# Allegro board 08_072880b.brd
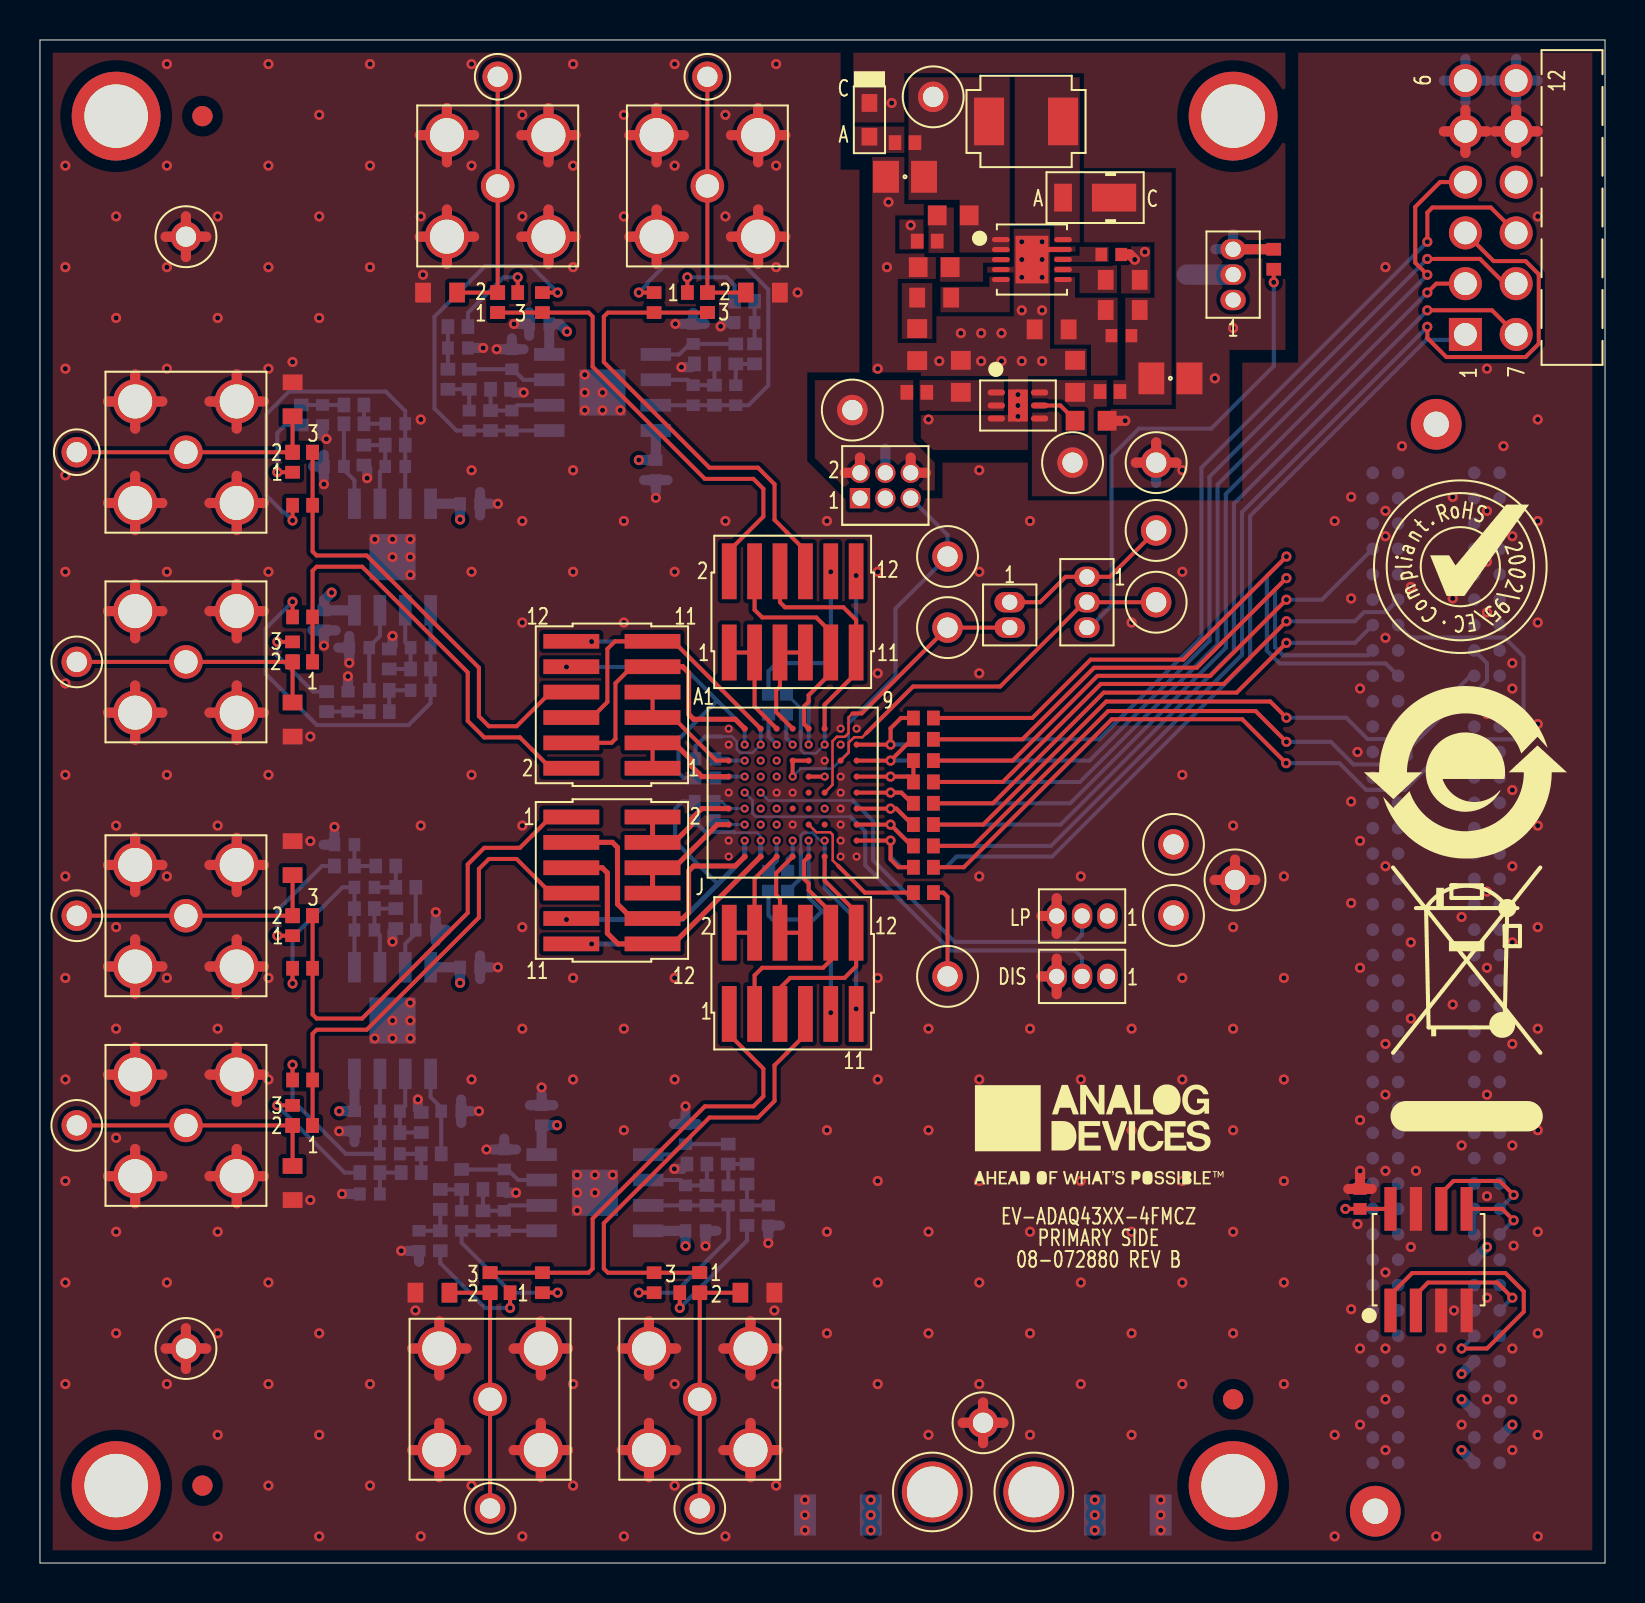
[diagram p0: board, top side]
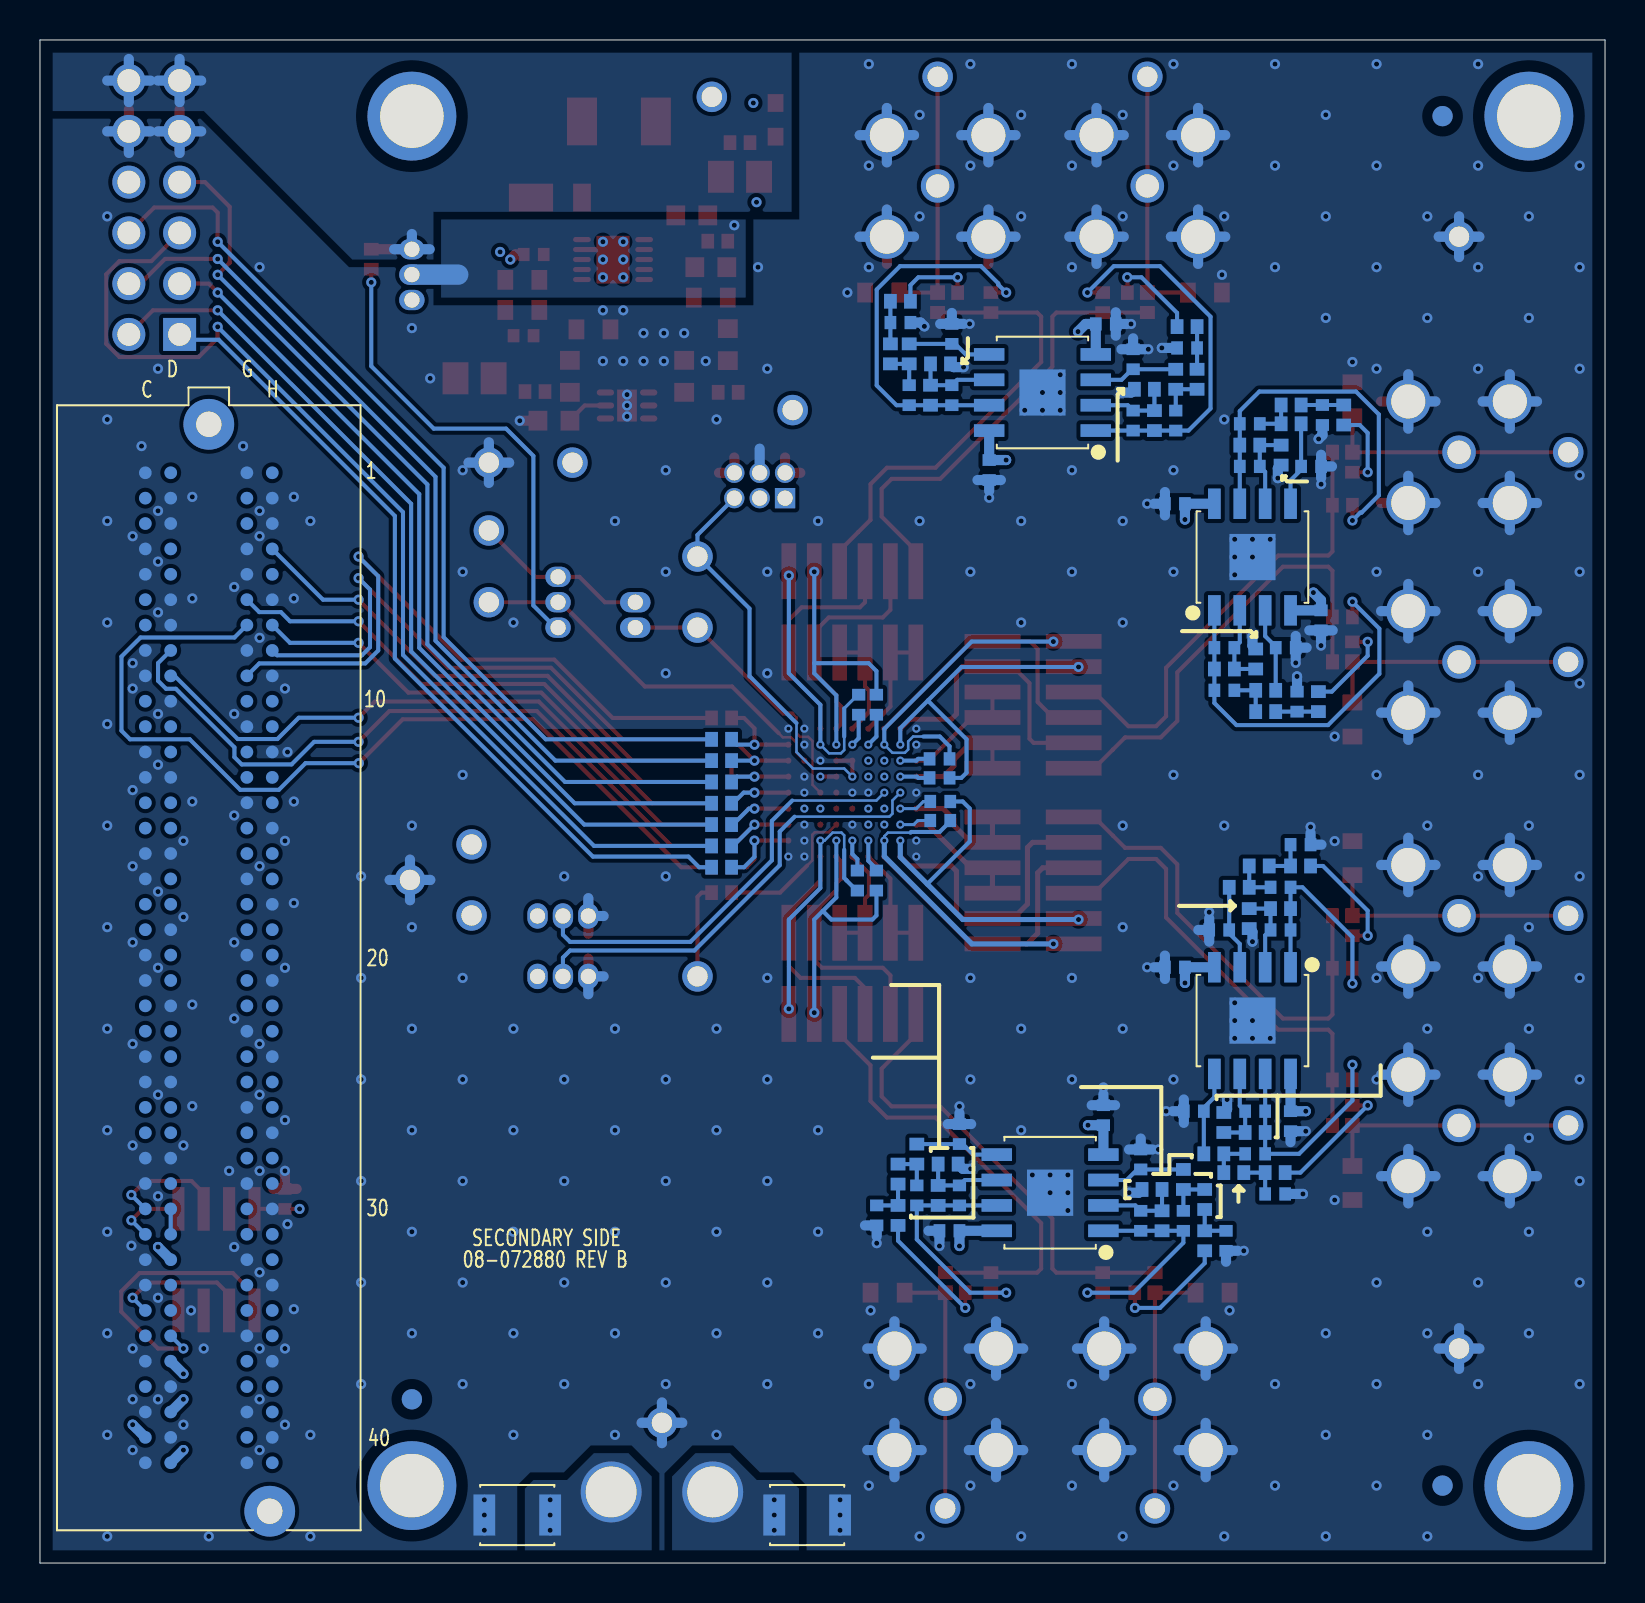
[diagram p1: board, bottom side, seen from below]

Outline 78.3 x 76.2 mm; copper layers: TOP, L2_GND, L3_PWR, BOTTOM. Coordinates in mm from the lower left corner of the outline.
Outline path: 0,76.2 0,0 78.3,0 78.3,76.2 0,76.2

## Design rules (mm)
constraint set DEFAULT: min track width 0.203
net group AINA: nets AINA+ AINA-
net group AINB: nets AINB+ AINB-
net group AINC: nets AINC+ AINC-
net group AIND: nets AIND+ AIND-

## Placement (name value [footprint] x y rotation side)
A1  ADA4625-2ARDZ  [SO8NB-PAD2_3X2_3]  27.76 18.53 90 bottom
A2  ADA4625-2ARDZ  [SO8NB-PAD2_3X2_3]  17.64 27.14 0 bottom
A3  ADA4625-2ARDZ  [SO8NB-PAD2_3X2_3]  17.64 50.33 180 bottom
A4  ADA4625-2ARDZ  [SO8NB-PAD2_3X2_3]  28.14 58.56 90 bottom
A+  RED  [CNKEY5001TP]  22.52 2.73 0 top
A-  RED  [CNKEY5001TP]  33.01 2.73 0 top
B+  RED  [CNKEY5001TP]  1.84 32.39 0 top
B-  RED  [CNKEY5001TP]  1.84 21.89 0 top
C1  TBD0402  [C0402]  36.45 34.15 270 bottom
C2  TBD0402  [C0402]  37.4 34.15 270 bottom
C3  TBD0402  [C0402]  33.26 38.1 180 bottom
C4  TBD0402  [C0402]  33.26 37.15 180 bottom
C5  TBD0402  [C0402]  33.29 39.28 180 bottom
C6  TBD0402  [C0402]  33.29 40.23 180 bottom
C7  TBD0402  [C0402]  36.45 42.94 90 bottom
C8  TBD0402  [C0402]  37.34 42.94 90 bottom
C9  0.1uF  [C0402]  66.04 18.22 90 top
C10  4.7UF  [C0805H60]  43.28 69.35 180 top
C11  2.2NF  [C0402]  53.59 65.47 180 top
C12  4.7UF  [C0805H60]  56.55 59.27 0 top
C13  2.2uF  [C0603]  51.78 59.37 90 top
C14  1NF  [C0603]  52.58 57.15 180 top
C15  2.2uF  [C0603]  46.07 59.37 90 top
C16  TBD0402  [C0402]  18.96 16.12 270 bottom
C17  TBD0402  [C0402]  36.44 17.39 270 bottom
C18  TBD0402  [C0402]  23.23 20.19 90 bottom
C19  TBD0402  [C0402]  32.3 21.46 90 bottom
C20  TBD0402  [C0402]  21.09 17.12 270 bottom
C21  TBD0402  [C0402]  34.43 18.39 270 bottom
C22  TBD0402  [C0402]  32.8 16.62 0 bottom
C23  TBD0402  [C0402]  25.1 22.41 90 bottom
C24  TBD0402  [C0402]  23.23 17.12 270 bottom
C25  TBD0402  [C0402]  32.3 18.39 270 bottom
C26  1uF  [C0603]  44.74 64.83 180 top
C27  150pF  [C0603]  43.88 60.96 90 top
C28  4.7pF  [C0402]  54.1 61.4 0 top
C29  TBD0402  [C0402]  15.23 35.94 180 bottom
C30  TBD0402  [C0402]  16.5 18.47 180 bottom
C31  TBD0402  [C0402]  19.3 31.67 0 bottom
C32  TBD0402  [C0402]  20.57 22.61 0 bottom
C33  TBD0402  [C0402]  16.23 33.81 180 bottom
C34  TBD0402  [C0402]  17.5 20.47 180 bottom
C35  TBD0402  [C0402]  15.73 22.11 270 bottom
C36  TBD0402  [C0402]  21.52 29.81 0 bottom
C37  TBD0402  [C0402]  16.23 31.67 180 bottom
C38  TBD0402  [C0402]  17.5 22.61 180 bottom
C39  TBD0402  [C0402]  15.41 43.1 90 bottom
C40  TBD0402  [C0402]  14.14 57.44 270 bottom
C41  TBD0402  [C0402]  15.97 45.8 180 bottom
C42  TBD0402  [C0402]  14.7 54.86 180 bottom
C43  TBD0402  [C0402]  19.04 43.66 0 bottom
C44  TBD0402  [C0402]  17.77 57 0 bottom
C45  TBD0402  [C0402]  21.52 53 0 bottom
C46  TBD0402  [C0402]  14.21 47.16 270 bottom
C47  TBD0402  [C0402]  19.04 45.8 0 bottom
C48  TBD0402  [C0402]  17.77 54.86 0 bottom
C49  TBD0402  [C0402]  20.91 60.79 0 bottom
C50  TBD0402  [C0402]  35.25 62.06 180 bottom
C51  TBD0402  [C0402]  23.61 60.23 90 bottom
C52  TBD0402  [C0402]  32.68 61.5 90 bottom
C53  TBD0402  [C0402]  21.48 57.16 270 bottom
C54  TBD0402  [C0402]  34.81 58.43 270 bottom
C55  TBD0402  [C0402]  30.81 54.68 270 bottom
C56  TBD0402  [C0402]  24.98 61.99 180 bottom
C57  TBD0402  [C0402]  23.61 57.16 270 bottom
C58  TBD0402  [C0402]  32.68 58.43 270 bottom
C59  10uF  [C1210H106]  39.92 2.4 180 bottom
C60  10uF  [C1210H106]  54.42 2.4 0 bottom
C+  RED  [CNKEY5001TP]  1.84 45.09 0 top
C-  RED  [CNKEY5001TP]  1.84 55.58 0 top
D1  DFLS260-7  [POWERDI123]  52.79 68.31 180 top
D+  RED  [CNKEY5001TP]  22.9 74.36 0 top
D-  RED  [CNKEY5001TP]  33.39 74.36 0 top
DS1  SML-D12P8WT86  [LED0603_A]  41.5 72.2 270 top
E1  600OHMS  [L0603]  45.69 67.42 180 top
ENABLE  FTS-103-01-F-S  [CN1X3H159]  53.4 29.35 180 top
GND1  BLK  [CNKEY5001TP]  55.84 55.05 0 top
GND2  BLK  [CNKEY5001TP]  59.79 34.18 0 top
GND3  BLK  [CNKEY5001TP]  7.3 10.73 0 top
GND4  BLK  [CNKEY5001TP]  47.18 7.02 0 top
GND5  BLK  [CNKEY5001TP]  7.3 66.36 0 top
IN_LDO  WHT  [CNKEY5001TP]  45.4 50.36 0 top
INA+  131-3701-261  [CNJOHNSON131-3701-261]  22.52 8.19 0 top
INA-  131-3701-261  [CNJOHNSON131-3701-261]  33.01 8.19 0 top
INB+  131-3701-261  [CNJOHNSON131-3701-261]  7.3 32.39 0 top
INB-  131-3701-261  [CNJOHNSON131-3701-261]  7.3 21.89 0 top
INC+  131-3701-261  [CNJOHNSON131-3701-261]  7.3 45.09 0 top
INC-  131-3701-261  [CNJOHNSON131-3701-261]  7.3 55.58 0 top
IND+  131-3701-261  [CNJOHNSON131-3701-261]  22.9 68.9 0 top
IND-  131-3701-261  [CNJOHNSON131-3701-261]  33.39 68.9 0 top
J1  FTS-103-01-F-S  [CN1X3H159]  59.69 63.19 90 top
J2  FTS-103-01-F-S  [CN1X3H159]  52.38 49.34 270 top
J3  FTS-103-01-F-D  [CNTHMHDR2X3L150W135H164]  41.02 53.28 0 top
JP1  0  [3PINJUMPER_0402]  22.52 13.53 270 top
JP2  0  [3PINJUMPER_0402]  33.01 13.53 0 top
JP3  JMPR_0402  [R0402]  25.13 14.03 90 top
JP4  JMPR_0402  [R0402]  30.72 14.03 90 top
JP5  0  [3PINJUMPER_0402]  12.64 32.39 180 top
JP6  0  [3PINJUMPER_0402]  12.64 21.89 270 top
JP7  JMPR_0402  [R0402]  13.14 29.76 0 top
JP8  JMPR_0402  [R0402]  13.14 24.17 0 top
JP9  0  [3PINJUMPER_0402]  12.64 45.09 270 top
JP10  0  [3PINJUMPER_0402]  12.64 55.58 180 top
JP11  JMPR_0402  [R0402]  13.14 47.33 0 top
JP12  JMPR_0402  [R0402]  13.14 52.92 0 top
JP13  0  [3PINJUMPER_0402]  22.9 63.56 180 top
JP14  0  [3PINJUMPER_0402]  33.39 63.56 90 top
JP15  JMPR_0402  [R0402]  25.13 63.06 270 top
JP16  JMPR_0402  [R0402]  30.72 63.06 270 top
L1  6.8UH  [LSMSQ160H79]  49.33 72.12 0 top
LKA  FTS-106-01-L-DV  [CNSMMHDR2X6L300W135H180]  37.66 29.5 0 top
LKB  FTS-106-01-L-DV  [CNSMMHDR2X6L300W135H180]  28.61 34.15 270 top
LKC  FTS-106-01-L-DV  [CNSMMHDR2X6L300W135H180]  28.61 42.94 90 top
LKD  FTS-106-01-L-DV  [CNSMMHDR2X6L300W135H180]  37.66 47.59 0 top
MODE  FTS-103-01-F-S  [CN1X3H159]  53.4 32.37 180 top
NOREF  -  []  2.1 0 0 top
NOREF#2  -  []  0 76.2 0 top
NOREF#3  -  [unnamed#2]  59.69 72.39 0 top
NOREF#4  -  []  0 76.2 0 top
NOREF#5  -  [unnamed#2]  8.13 3.87 0 top
NOREF#6  -  []  -107.38 -168.53 0 top
NOREF#7  -  []  94.21 -80.45 0 top
NOREF#8  -  []  78.3 76.2 180 top
NOREF#9  -  []  80.64 38.48 0 top
NOREF#10  -  []  59.86 -66.1 180 top
NOREF#11  -  []  78.3 0 0 top
NOREF#12  -  []  253.56 264.16 270 top
NOREF#13  -  []  -107.38 -168.53 0 top
NOREF#14  -  [unnamed#2]  59.69 3.87 0 top
NOREF#15  -  []  78.3 0 90 top
NOREF#16  -  []  2.1 76.2 270 top
NOREF#17  -  []  94.24 -56.32 0 top
NOREF#18  -  []  3.81 3.87 0 top
NOREF#19  -  []  71.06 49.85 0 top
NOREF#20  -  []  -107.38 -168.53 0 top
NOREF#21  -  []  502.48 43.18 0 top
NOREF#22  -  []  52.68 21.4 0 top
NOREF#23  -  [unnamed#2]  59.69 8.19 0 top
NOREF#24  -  [unnamed#2]  3.81 3.87 0 top
NOREF#25  -  [unnamed#2]  8.13 72.39 0 top
NOREF#26  -  []  94.24 -56.32 0 top
NOREF#27  -  []  -37.15 209.23 0 top
NOREF#28  -  []  0 0 0 top
NOREF#29  -  []  93.96 -18.22 0 top
NOREF#30  -  []  78.3 0 90 top
NOREF#31  -  [unnamed#2]  3.81 72.39 0 top
NOREF#32  -  []  5.38 74.74 0 top
NOREF#33  -  []  105.98 106.68 0 top
NOREF#34  -  []  45.49 1.39 0 top
NOREF#35  -  []  71.31 39.56 0 top
NOREF#36  -  []  253.56 303.53 0 top
NOREF#37  -  []  3.81 3.87 0 top
NOREF#38  -  []  0 0 0 top
NOREF#39  -  [unnamed#2]  8.13 72.39 180 bottom
NOREF#40  -  [unnamed#2]  8.13 3.87 180 bottom
NOREF#41  -  [unnamed#2]  59.69 8.19 180 bottom
OUT_LDO  RED  [CNKEY5001TP]  55.84 51.66 0 top
P1  ASP-134604-01  [CNSAMTECASP-134604-01]  69.85 29.78 270 bottom
P2  TSW-106-25-F-D-RA  [CNHDRRA2X6H240]  71.31 61.47 90 top
P3  FTS-102-01-F-S  [CNSAMTECFTS-102-01-F-S]  48.51 48.07 270 top
R1  TBD0603  [R0603]  19.63 13.53 0 top
R2  TBD0603  [R0603]  35.89 13.53 180 top
R3  TBD0603  [R0603]  12.64 35.27 270 top
R4  TBD0603  [R0603]  12.64 19.01 90 top
R5  TBD0603  [R0603]  12.64 42.2 90 top
R6  TBD0603  [R0603]  12.64 58.22 270 top
R7  TBD0603  [R0603]  20.02 63.56 0 top
R8  TBD0603  [R0603]  36.16 63.56 180 top
R9  TBD0402  [R0402]  20.03 16.12 90 bottom
R10  0  [R0402]  61.72 65.23 270 top
R11  TBD0402  [R0402]  35.37 17.39 90 bottom
R12  TBD0402  [R0402]  20.03 18.19 90 bottom
R13  0  [R0402]  44.2 35.88 0 top
R14  0  [R0402]  44.2 36.94 0 top
R15  0  [R0402]  44.2 39.08 0 top
R16  0  [R0402]  44.2 34.81 0 top
R17  0  [R0402]  44.2 42.28 0 top
R18  TBD0402  [R0402]  35.37 19.46 90 bottom
R19  0  [R0402]  44.2 38.01 0 top
R20  0  [R0402]  44.2 41.21 0 top
R21  TBD0402  [R0402]  21.09 19.19 90 bottom
R22  TBD0402  [R0402]  34.43 20.46 90 bottom
R23  0  [R0402]  44.2 40.14 0 top
R24  0  [R0402]  44.2 34.81 0 bottom
R25  0  [R0402]  44.2 38.01 0 bottom
R26  0  [R0402]  44.2 35.88 0 bottom
R27  0  [R0402]  44.2 39.08 0 bottom
R28  0  [R0402]  44.2 36.94 180 bottom
R29  0  [R0402]  44.2 40.14 180 bottom
R30  TBD0402  [R0402]  22.66 18.69 180 bottom
R31  97.6K  [R0603]  54.17 62.69 180 top
R32  34.8K  [R0603]  50.61 61.72 180 top
R33  0  [R0402]  53.53 58.61 180 top
R34  200  [R0402]  43.28 71.06 0 top
R35  TBD0402  [R0402]  32.86 19.96 0 bottom
R36  TBD0402  [R0402]  22.16 17.12 270 bottom
R37  TBD0402  [R0402]  33.36 18.39 270 bottom
R38  TBD0402  [R0402]  15.23 34.87 0 bottom
R39  TBD0402  [R0402]  16.5 19.53 0 bottom
R40  0  [R0402]  13.14 21.89 0 top
R41  TBD0402  [R0402]  17.3 34.87 0 bottom
R42  TBD0402  [R0402]  18.57 19.53 0 bottom
R43  0  [R0402]  13.14 32.39 0 top
R44  TBD0402  [R0402]  18.3 33.81 0 bottom
R45  TBD0402  [R0402]  19.57 20.47 0 bottom
R46  TBD0402  [R0402]  17.8 32.24 90 bottom
R47  TBD0402  [R0402]  19.07 22.04 270 bottom
R48  TBD0402  [R0402]  16.23 32.74 180 bottom
R49  TBD0402  [R0402]  17.5 21.54 180 bottom
R50  TBD0402  [R0402]  14.34 43.1 270 bottom
R51  20K  [R0603]  54.17 64.2 0 top
R52  56.2K  [R0603]  44.74 63.31 180 top
R53  0  [R0402]  44.39 66.14 0 top
R54  0  [R0402]  43.87 58.57 180 top
R55  TBD0402  [R0402]  13.07 57.44 90 bottom
R56  0  [R0402]  13.14 55.58 0 top
R57  TBD0402  [R0402]  16.97 42.6 0 bottom
R58  TBD0402  [R0402]  15.7 57.94 0 bottom
R59  0  [R0402]  13.14 45.09 0 top
R60  TBD0402  [R0402]  16.97 43.66 180 bottom
R61  TBD0402  [R0402]  15.7 57 180 bottom
R62  TBD0402  [R0402]  17.48 45.23 270 bottom
R63  TBD0402  [R0402]  16.21 55.43 90 bottom
R64  TBD0402  [R0402]  19.04 44.73 0 bottom
R65  TBD0402  [R0402]  17.77 55.93 0 bottom
R66  TBD0402  [R0402]  20.91 61.86 180 bottom
R67  TBD0402  [R0402]  35.25 63.13 0 bottom
R68  0  [R0402]  44.2 41.21 180 bottom
R69  0  [R0402]  33.39 63.06 270 top
R70  0  [R0402]  22.52 14.03 90 top
R71  0  [R0402]  33.01 14.03 90 top
R72  TBD0402  [R0402]  20.41 59.23 270 bottom
R73  TBD0402  [R0402]  35.75 60.5 270 bottom
R74  0  [R0402]  22.9 63.06 270 top
R75  TBD0402  [R0402]  21.48 59.23 90 bottom
R76  TBD0402  [R0402]  34.81 60.5 90 bottom
R77  TBD0402  [R0402]  23.04 58.72 180 bottom
R78  TBD0402  [R0402]  33.24 59.99 0 bottom
R79  TBD0402  [R0402]  22.54 57.16 270 bottom
R80  TBD0402  [R0402]  33.74 58.43 270 bottom
R81  TBD0402  [R0402]  44.2 33.54 0 top
REFS  WHT  [CNKEY5001TP]  45.4 29.35 0 top
U1  ADAQ4380-4  [BGA81H91]  37.66 38.54 270 top
U2  LT8362EDD#PBF  [DFN10_3X3_PAD2_38X1_64]  49.63 65.21 270 top
U3  ADP7142ACPZN5.0  [DFN6_2X2_PAD1_6X1]  48.93 57.91 270 top
U4  M24C02-RMN6TP  [SO8]  69.47 15.18 0 top
UNK3V3  RED  [CNKEY5001TP]  44.68 73.36 0 top
UNK+5V  RED  [CNKEY5001TP]  40.64 57.68 0 top
UNK+6V  RED  [CNKEY5001TP]  51.66 55.05 0 top
VCC  RED  [CNKEY5001TP]  45.4 46.8 0 top
VLOGIC  WHT  [CNKEY5001TP]  55.84 48.07 0 top
VNEG  2501-2-00-80-00-00-07-0  [CNMILLMAX2501]  49.72 3.56 0 top
VPOS  2501-2-00-80-00-00-07-0  [CNMILLMAX2501]  44.64 3.56 0 top
VS+  RED  [CNKEY5001TP]  56.71 32.4 0 top
VS-  ORG  [CNKEY5001TP]  56.71 35.95 0 top

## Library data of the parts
A1-A4 = ADA4625_2_V2: Tolerance: N/A; User Part Number: UPN; alternate symbols: (); part number: ADA4625_2_V2_SM-ADA4625-2ARDZ,E031176,SO8NB-PAD2_3X2_3; tolerance: N/A
A+ A- B+ B- C+ C- D+ D- OUT_LDO UNK3V3 UNK+5V UNK+6V VCC VS+ = CNTP1P: Tolerance: N/A; User Part Number: UPN; alternate symbols: (); part number: CNTP1P_TH-RED,E016323,CNKEY5001TP; tolerance: N/A
C1-C8 C16-C25 C29-C58 = CAP: User Part Number: UPN; alternate symbols: (C0402L_ALT,C0402L); part number: CAP_SM-TBD0402,TBD0402,TBD0402,E000381,C0402
C9 = CAP: User Part Number: UPN; Tolerance: 10; alternate symbols: (C0402L); part number: CAP_SM-0.1UF,16V,10,E028141,C0402; tolerance: 10
C10 C12 = CAP: Tolerance: 10; User Part Number: UPN; alternate symbols: (); part number: CAP_SM-4.7UF,16V,10,E058535,C0805H60; tolerance: 10
C11 = CAP: User Part Number: UPN; Tolerance: 20; alternate symbols: (C0402L); part number: CAP_SM-2.2NF,25V,20,E042791,C0402; tolerance: 20
C13 C15 = CAP: User Part Number: UPN; Tolerance: 10; alternate symbols: (C0603L); part number: CAP_SM-2.2UF,25V,10,E039850,C0603; tolerance: 10
C14 = CAP: User Part Number: UPN; Tolerance: 10; alternate symbols: (C0603L); part number: CAP_SM-1NF,100V,10,E042847,C0603; tolerance: 10
C26 = CAP: User Part Number: UPN; Tolerance: 10; alternate symbols: (C0603L); part number: CAP_SM-1UF,25V,10,E033832,C0603; tolerance: 10
C27 = CAP: User Part Number: UPN; Tolerance: 5; alternate symbols: (C0603L); part number: CAP_SM-150PF,50V,5,E030220,C0603; tolerance: 5
C28 = CAP: User Part Number: UPN; Tolerance: 0.05pF; alternate symbols: (C0402L); part number: CAP_SM-4.7PF,50V,0.05PF,E021938,C0402; tolerance: 0.05pF
C59 C60 = CAP: Tolerance: 10; User Part Number: UPN; alternate symbols: (); part number: CAP_SM-10UF,25V,10,E013830,C1210H106; tolerance: 10
D1 = DIOSCHOTTKY: User Part Number: UPN; Tolerance: N/A; alternate symbols: (); part number: DIOSCHOTTKY_SM-DFLS260-7,60V,N/A,E032987,POWERDI123; tolerance: N/A
DS1 = DIOLED: User Part Number: UPN; Tolerance: N/A; alternate symbols: (); part number: DIOLED_SM-SML-D12P8WT86,2.2V,N/A,E027457,LED0603_A; tolerance: N/A
E1 = FERRITE: User Part Number: UPN; Tolerance: 25; alternate symbols: (L0603L); part number: FERRITE_SM-600OHMS,25,E007179,L0603; tolerance: 25
ENABLE J1 J2 MODE = CN3P: Tolerance: N/A; User Part Number: UPN; alternate symbols: (); part number: CN3P_TH-FTS-103-01-F-S,E021702,CN1X3H159; tolerance: N/A
GND1-GND5 = CNTP1P: Tolerance: N/A; User Part Number: UPN; alternate symbols: (); part number: CNTP1P_TH-BLK,E005347,CNKEY5001TP; tolerance: N/A
IN_LDO REFS VLOGIC = CNTP1P: Tolerance: N/A; User Part Number: UPN; alternate symbols: (); part number: CNTP1P_TH-WHT,E006153,CNKEY5001TP; tolerance: N/A
INA+ INA- INB+ INB- INC+ INC- IND+ IND- = CNBNC5P: Tolerance: N/A; User Part Number: UPN; alternate symbols: (); part number: CNBNC5P_TH-131-3701-261,E012123,CNJOHNSON131-3701-261; tolerance: N/A
J3 = CN6P_ODD_EVEN: User Part Number: UPN; Tolerance: N/A; alternate symbols: (); part number: CN6P_ODD_EVEN_TH-FTS-103-01-F-D,E047281,CNTHMHDR2X3L150W135H164; tolerance: N/A
JP1 JP2 JP5 JP6 JP9 JP10 JP13 JP14 = RESJMPR_3P: User Part Number: UPN; Tolerance: JUMPER; alternate symbols: (3PINJUMPER_0402_AB, 3PINJUMPER_0402_BA); part number: RESJMPR_3P_SM-0,E003438,1/10W,JUMPER,3PINJUMPER_0402; tolerance: JUMPER
JP3 JP4 JP7 JP8 JP11 JP12 JP15 JP16 = RESJMPRSHRT: User Part Number: UPN; Tolerance: N/A; alternate symbols: (R0402L); part number: RESJMPRSHRT_SM-JMPR_0402,E039547,N/A,N/A,R0402; tolerance: N/A
L1 = IND: User Part Number: UPN; Tolerance: 20; alternate symbols: (); part number: IND_SM-6.8UH,20,E035159,LSMSQ160H79; tolerance: 20
LKA LKB LKC LKD = CN12P_ODD_EVEN: User Part Number: UPN; Tolerance: N/A; alternate symbols: (); part number: CN12P_ODD_EVEN_SM-FTS-106-01-L-DV,E049458,CNSMMHDR2X6L300W135H180; tolerance: N/A
P1 = CN160P_CDGH: User Part Number: UPN; Tolerance: N/A; alternate symbols: (CNSAMTECASP-134604-01_KITTRF); part number: CN160P_CDGH_SM-ASP-134604-01,E011383,CNSAMTECASP-134604-01; tolerance: N/A
P2 = CN12P_V3: User Part Number: UPN; Tolerance: N/A; alternate symbols: (); part number: CN12P_V3_TH-TSW-106-25-F-D-RA,E018495,CNHDRRA2X6H240; tolerance: N/A
P3 = CN2P: Tolerance: N/A; User Part Number: UPN; alternate symbols: (); part number: CN2P_TH-FTS-102-01-F-S,E021754,CNSAMTECFTS-102-01-F-S; tolerance: N/A
R1-R8 = RES: User Part Number: UPN; alternate symbols: (R0603L); part number: RES_SM-TBD0603,E004050,TBD0603,TBD0603,R0603
R9 R11 R12 R18 R21 R22 R30 R35-R39 R41 R42 R44-R50 R55 R57 R58 R60-R67 R72 R73 R75-R81 = RES: User Part Number: UPN; alternate symbols: (R0402L,R0402L_ALT); part number: RES_SM-TBD0402,E004049,TBD0402,TBD0402,R0402
R10 R33 R53 R54 = RES: User Part Number: UPN; Tolerance: JUMPER; alternate symbols: (R0402L); part number: RES_SM-0,E025232,1/16W,JUMPER,R0402; tolerance: JUMPER
R13-R17 R19 R20 R23-R29 R40 R43 R56 R59 R68-R71 R74 = RES: User Part Number: UPN; Tolerance: JUMPER; alternate symbols: (R0402L,R0402L_ALT); part number: RES_SM-0,E003438,1/10W,JUMPER,R0402; tolerance: JUMPER
R31 = RES: User Part Number: UPN; Tolerance: 1; alternate symbols: (R0603L); part number: RES_SM-97.6K,E031992,1/10W,1,R0603; tolerance: 1
R32 = RES: User Part Number: UPN; Tolerance: 1; alternate symbols: (R0603L); part number: RES_SM-34.8K,E036013,1/10W,1,R0603; tolerance: 1
R34 = RES: User Part Number: UPN; Tolerance: 1; alternate symbols: (R0402L); part number: RES_SM-200,E003753,1/10W,1,R0402; tolerance: 1
R51 = RES: User Part Number: UPN; Tolerance: 1; alternate symbols: (R0603L); part number: RES_SM-20K,E017927,1/10W,1,R0603; tolerance: 1
R52 = RES: User Part Number: UPN; Tolerance: 1; alternate symbols: (R0603L); part number: RES_SM-56.2K,E003709,1/10W,1,R0603; tolerance: 1
U1 = ADAQ4380_4: User Part Number: UPN; Tolerance: N/A; alternate symbols: (); part number: ADAQ4380_4_SM-ADAQ4380-4,E046961,BGA81H91; tolerance: N/A
U2 = ICLT8362: Tolerance: N/A; User Part Number: UPN; alternate symbols: (); part number: ICLT8362_SM-LT8362EDD#PBF,E033516,DFN10_3X3_PAD2_38X1_64; tolerance: N/A
U3 = ADP7142: User Part Number: UPN; Tolerance: N/A; alternate symbols: (); part number: ADP7142_SM-ADP7142ACPZN5.0,E023519,DFN6_2X2_PAD1_6X1; tolerance: N/A
U4 = ICM24CXX: Tolerance: N/A; User Part Number: UPN; alternate symbols: (); part number: ICM24CXX_SM-M24C02-RMN6TP,E018349,SO8; tolerance: N/A
VNEG VPOS = CNTP1P: User Part Number: UPN; Tolerance: N/A; alternate symbols: (); part number: CNTP1P_TH-2501-2-00-80-00-00-07-0,E031108,CNMILLMAX2501; tolerance: N/A
VS- = CNTP1P: Tolerance: N/A; User Part Number: UPN; alternate symbols: (); part number: CNTP1P_TH-ORG,E029026,CNKEY5001TP; tolerance: N/A

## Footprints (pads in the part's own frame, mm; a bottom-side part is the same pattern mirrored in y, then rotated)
3PINJUMPER_0402
  rect 0.737x0.635 smd: 1(0,1.001)
  rect 0.737x0.737 smd: 2(0,0)
  rect 0.635x0.737 smd: 3(-1.001,0)
BGA81H91
  round 0.305 smd: A1(-3.2,-3.2) A2(-3.2,-2.4) A3(-3.2,-1.6) A4(-3.2,-0.8) A5(-3.2,0) A6(-3.2,0.8) A7(-3.2,1.6) A8(-3.2,2.4) A9(-3.2,3.2) B1(-2.4,-3.2) B2(-2.4,-2.4) B3(-2.4,-1.6) B4(-2.4,-0.8) B5(-2.4,0) B6(-2.4,0.8) B7(-2.4,1.6) B8(-2.4,2.4) B9(-2.4,3.2) C1(-1.6,-3.2) C2(-1.6,-2.4) C3(-1.6,-1.6) C4(-1.6,-0.8) C5(-1.6,0) C6(-1.6,0.8) C7(-1.6,1.6) C8(-1.6,2.4) C9(-1.6,3.2) D1(-0.8,-3.2) D2(-0.8,-2.4) D3(-0.8,-1.6) D4(-0.8,-0.8) D5(-0.8,0) D6(-0.8,0.8) D7(-0.8,1.6) D8(-0.8,2.4) D9(-0.8,3.2) E1(0,-3.2) E2(0,-2.4) E3(0,-1.6) E4(0,-0.8) E5(0,0) E6(0,0.8) E7(0,1.6) E8(0,2.4) E9(0,3.2) F1(0.8,-3.2) F2(0.8,-2.4) F3(0.8,-1.6) F4(0.8,-0.8) F5(0.8,0) F6(0.8,0.8) F7(0.8,1.6) F8(0.8,2.4) F9(0.8,3.2) G1(1.6,-3.2) G2(1.6,-2.4) G3(1.6,-1.6) G4(1.6,-0.8) G5(1.6,0) G6(1.6,0.8) G7(1.6,1.6) G8(1.6,2.4) G9(1.6,3.2) H1(2.4,-3.2) H2(2.4,-2.4) H3(2.4,-1.6) H4(2.4,-0.8) H5(2.4,0) H6(2.4,0.8) H7(2.4,1.6) H8(2.4,2.4) H9(2.4,3.2) J1(3.2,-3.2) J2(3.2,-2.4) J3(3.2,-1.6) J4(3.2,-0.8) J5(3.2,0) J6(3.2,0.8) J7(3.2,1.6) J8(3.2,2.4) J9(3.2,3.2)
C0402
  rect 0.584x0.66 smd: 1(-0.5,0) 2(0.5,0)
C0603
  rect 0.94x0.991 smd: 1(-0.8,0) 2(0.8,0)
C0805H60
  rect 1.295x1.6 smd: 1(-0.953,0) 2(0.953,0)
C1210H106
  rect 1.092x2.057 smd: 1(-1.646,0) 2(1.646,0)
CN1X3H159
  oval 1.016x1.27 hole 0.762: 1(0,0) 2(1.27,0) 3(2.54,0)
CNHDRRA2X6H240
  rect 1.651x1.651 hole 1.143: 1(0,0)
  round 1.651 hole 1.143: 2(2.54,0) 3(5.08,0) 4(7.62,0) 5(10.16,0) 6(12.7,0) 7(0,-2.54) 8(2.54,-2.54) 9(5.08,-2.54) 10(7.62,-2.54) 11(10.16,-2.54) 12(12.7,-2.54)
CNJOHNSON131-3701-261
  round 1.676 hole 1.168: 1(0,0)
  round 2.21 hole 1.702: 2(-2.54,2.54) 3(2.54,2.54) 4(2.54,-2.54) 5(-2.54,-2.54)
CNKEY5001TP
  round 1.524 hole 1.016: 1(0,0)
CNMILLMAX2501
  round 3.048 hole 2.54: 1(0,0)
CNSAMTECASP-134604-01
  round 2.54 hole 1.27 unplated: (-27.191,0) (27.191,3.048)
  round 0.635 smd: C1(-24.765,-3.175) C2(-23.495,-3.175) C3(-22.225,-3.175) C4(-20.955,-3.175) C5(-19.685,-3.175) C6(-18.415,-3.175) C7(-17.145,-3.175) C8(-15.875,-3.175) C9(-14.605,-3.175) C10(-13.335,-3.175) C11(-12.065,-3.175) C12(-10.795,-3.175) C13(-9.525,-3.175) C14(-8.255,-3.175) C15(-6.985,-3.175) C16(-5.715,-3.175) C17(-4.445,-3.175) C18(-3.175,-3.175) C19(-1.905,-3.175) C20(-0.635,-3.175) C21(0.635,-3.175) C22(1.905,-3.175) C23(3.175,-3.175) C24(4.445,-3.175) C25(5.715,-3.175) C26(6.985,-3.175) C27(8.255,-3.175) C28(9.525,-3.175) C29(10.795,-3.175) C30(12.065,-3.175) C31(13.335,-3.175) C32(14.605,-3.175) C33(15.875,-3.175) C34(17.145,-3.175) C35(18.415,-3.175) C36(19.685,-3.175) C37(20.955,-3.175) C38(22.225,-3.175) C39(23.495,-3.175) C40(24.765,-3.175) D1(-24.765,-1.905) D2(-23.495,-1.905) D3(-22.225,-1.905) D4(-20.955,-1.905) D5(-19.685,-1.905) D6(-18.415,-1.905) D7(-17.145,-1.905) D8(-15.875,-1.905) D9(-14.605,-1.905) D10(-13.335,-1.905) D11(-12.065,-1.905) D12(-10.795,-1.905) D13(-9.525,-1.905) D14(-8.255,-1.905) D15(-6.985,-1.905) D16(-5.715,-1.905) D17(-4.445,-1.905) D18(-3.175,-1.905) D19(-1.905,-1.905) D20(-0.635,-1.905) D21(0.635,-1.905) D22(1.905,-1.905) D23(3.175,-1.905) D24(4.445,-1.905) D25(5.715,-1.905) D26(6.985,-1.905) D27(8.255,-1.905) D28(9.525,-1.905) D29(10.795,-1.905) D30(12.065,-1.905) D31(13.335,-1.905) D32(14.605,-1.905) D33(15.875,-1.905) D34(17.145,-1.905) D35(18.415,-1.905) D36(19.685,-1.905) D37(20.955,-1.905) D38(22.225,-1.905) D39(23.495,-1.905) D40(24.765,-1.905) G1(-24.765,1.905) G2(-23.495,1.905) G3(-22.225,1.905) G4(-20.955,1.905) G5(-19.685,1.905) G6(-18.415,1.905) G7(-17.145,1.905) G8(-15.875,1.905) G9(-14.605,1.905) G10(-13.335,1.905) G11(-12.065,1.905) G12(-10.795,1.905) G13(-9.525,1.905) G14(-8.255,1.905) G15(-6.985,1.905) G16(-5.715,1.905) G17(-4.445,1.905) G18(-3.175,1.905) G19(-1.905,1.905) G20(-0.635,1.905) G21(0.635,1.905) G22(1.905,1.905) G23(3.175,1.905) G24(4.445,1.905) G25(5.715,1.905) G26(6.985,1.905) G27(8.255,1.905) G28(9.525,1.905) G29(10.795,1.905) G30(12.065,1.905) G31(13.335,1.905) G32(14.605,1.905) G33(15.875,1.905) G34(17.145,1.905) G35(18.415,1.905) G36(19.685,1.905) G37(20.955,1.905) G38(22.225,1.905) G39(23.495,1.905) G40(24.765,1.905) H1(-24.765,3.175) H2(-23.495,3.175) H3(-22.225,3.175) H4(-20.955,3.175) H5(-19.685,3.175) H6(-18.415,3.175) H7(-17.145,3.175) H8(-15.875,3.175) H9(-14.605,3.175) H10(-13.335,3.175) H11(-12.065,3.175) H12(-10.795,3.175) H13(-9.525,3.175) H14(-8.255,3.175) H15(-6.985,3.175) H16(-5.715,3.175) H17(-4.445,3.175) H18(-3.175,3.175) H19(-1.905,3.175) H20(-0.635,3.175) H21(0.635,3.175) H22(1.905,3.175) H23(3.175,3.175) H24(4.445,3.175) H25(5.715,3.175) H26(6.985,3.175) H27(8.255,3.175) H28(9.525,3.175) H29(10.795,3.175) H30(12.065,3.175) H31(13.335,3.175) H32(14.605,3.175) H33(15.875,3.175) H34(17.145,3.175) H35(18.415,3.175) H36(19.685,3.175) H37(20.955,3.175) H38(22.225,3.175) H39(23.495,3.175) H40(24.765,3.175)
CNSAMTECFTS-102-01-F-S
  oval 1.016x1.524 hole 0.762: 1(0,0) 2(1.27,0)
CNSMMHDR2X6L300W135H180
  rect 0.737x2.794 smd: 1(-3.175,-2.032) 2(-3.175,2.032) 3(-1.905,-2.032) 4(-1.905,2.032) 5(-0.635,-2.032) 6(-0.635,2.032) 7(0.635,-2.032) 8(0.635,2.032) 9(1.905,-2.032) 10(1.905,2.032) 11(3.175,-2.032) 12(3.175,2.032)
CNTHMHDR2X3L150W135H164
  rect 1.016x1.016 hole 0.762: 1(0,0)
  round 1.016 hole 0.762: 2(0,1.27) 3(1.27,0) 4(1.27,1.27) 5(2.54,0) 6(2.54,1.27)
DFN6_2X2_PAD1_6X1
  oval 0.305x0.864 smd: 1(-0.65,-1.082) 2(0,-1.082) 3(0.65,-1.082) 4(0.65,1.082) 5(0,1.082) 6(-0.65,1.082)
  rect 1.6x0.991 smd: PAD(0,0)
DFN10_3X3_PAD2_38X1_64
  oval 0.254x0.889 smd: 1(-1,-1.555) 2(-0.5,-1.555) 3(0,-1.555) 4(0.5,-1.555) 5(1,-1.555) 6(1,1.555) 7(0.5,1.555) 8(0,1.555) 9(-0.5,1.555) 10(-1,1.555)
  rect 2.388x1.651 smd: PAD(0,0)
L0603
  rect 0.94x0.991 smd: 1(-0.8,0) 2(0.8,0)
LED0603_A
  rect 0.889x0.787 smd: A(0.843,0) C(-0.843,0)
LSMSQ160H79
  rect 1.499x2.388 smd: 1(-1.849,0) 2(1.849,0)
POWERDI123
  rect 0.889x1.397 smd: A(1.606,0)
  rect 2.21x1.397 smd: C(-0.945,0)
R0402
  rect 0.635x0.737 smd: 1(-0.5,0) 2(0.5,0)
R0603
  rect 0.787x0.991 smd: 1(-0.851,0) 2(0.851,0)
SO8
  rect 0.61x2.184 smd: 1(-1.905,-2.54) 2(-0.635,-2.54) 3(0.635,-2.54) 4(1.905,-2.54) 5(1.905,2.54) 6(0.635,2.54) 7(-0.635,2.54) 8(-1.905,2.54)
SO8NB-PAD2_3X2_3
  rect 0.635x1.524 smd: 1(-1.905,-2.667) 2(-0.635,-2.667) 3(0.635,-2.667) 4(1.905,-2.667) 5(1.905,2.667) 6(0.635,2.667) 7(-0.635,2.667) 8(-1.905,2.667)
  rect 2.311x2.311 smd: PAD(0,0)
unnamed#2
  round 4.445 hole 3.175 unplated: (0,0)

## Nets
3V3IN: J1.2 R53.1
+3V3_FMC: J1.1 P1.C39 P1.D36 P1.D38 P1.D40
+3V3_PMOD: J1.3(N3) P2.6 P2.12(VCC2) R10.1
AGND: A1.PAD A2.PAD A3.PAD A4.PAD C9.2(N2) C10.2(N2) C11.1 C12.2(N2) C13.2(N2) C14.1 C15.2(N2) C16.2(N2) C17.2(N2) C18.2(N2) C19.2(N2) C22.2(N2) C23.2(N2) C26.2(N2) C27.1 C29.2(N2) C30.2(N2) C31.2(N2) C32.2(N2) C35.2(N2) C36.2(N2) C39.2(N2) C40.2(N2) C41.2(N2) C42.2(N2) C45.2(N2) C46.2(N2) C49.2(N2) C50.2(N2) C51.2(N2) C52.2(N2) C55.2(N2) C56.2(N2) C59.2(N2) C60.2(N2) DS1.C ENABLE.3(N3) GND1.1(N1) GND2.1(N1) GND3.1(N1) GND4.1(N1) GND5.1(N1) INA+.2 INA+.3 INA+.4 INA+.5(SH4) INA-.2 INA-.3 INA-.4 INA-.5(SH4) INB+.2 INB+.3 INB+.4 INB+.5(SH4) INB-.2 INB-.3 INB-.4 INB-.5(SH4) INC+.2 INC+.3 INC+.4 INC+.5(SH4) INC-.2 INC-.3 INC-.4 INC-.5(SH4) IND+.2 IND+.3 IND+.4 IND+.5(SH4) IND-.2 IND-.3 IND-.4 IND-.5(SH4) J3.4 MODE.3(N3) P1.C1 P1.C4 P1.C5 P1.C8 P1.C9 P1.C12 P1.C13 P1.C16 P1.C17 P1.C20 P1.C21 P1.C24 P1.C25 P1.C28 P1.C29 P1.C32 P1.C33 P1.C36 P1.C38 P1.C40 P1.D2 P1.D3 P1.D6 P1.D7 P1.D10 P1.D13 P1.D16 P1.D19 P1.D22 P1.D25 P1.D28 P1.D37 P1.D39 P1.G1 P1.G4 P1.G5 P1.G8 P1.G11 P1.G14 P1.G17 P1.G20 P1.G23 P1.G26 P1.G29 P1.G32 P1.G35 P1.G38 P1.G40 P1.H2 P1.H3 P1.H6 P1.H9(N9) P1.H12 P1.H15 P1.H18 P1.H21 P1.H24 P1.H27 P1.H30 P1.H33 P1.H36 P1.H39 P2.5 P2.11 R1.1 R2.1 R3.1 R4.1 R5.1 R6.1 R7.1 R8.1 R30.1 R32.2(N2) R35.1 R46.1 R47.1 R51.2(N2) R62.1 R63.1 R77.1 R78.1 U1.A1 U1.A8 U1.A9 U1.B1 U1.B8 U1.C7 U1.D8 U1.E1 U1.E4 U1.E5 U1.E8 U1.F8 U1.G5 U1.G8 U1.H1 U1.H8 U1.J1 U1.J8 U1.J9 U2.4 U2.9 U2.PAD U3.3 U3.PAD U4.3 U4.4 U4.7(WC_N)
P5V0: J3.2 J3.6(N6) R54.2(N2) UNK+5V.1
VCC: P3.2(N2) U1.E7 VCC.1(N1)
3P3VAUX: C9.1 P1.D32 U4.8
AINA+: JP1.3 JP3.2(S2) LKA.1 R70.2(N2)
AINA-: JP2.1 JP4.2(S2) LKA.7 R71.2(N2)
AINB+: JP5.3 JP7.2(S2) LKB.1 R43.2(N2)
AINB-: JP6.1 JP8.2(S2) LKB.7 R40.2(N2)
AINC+: JP9.1 JP11.2(S2) LKC.2 R59.2(N2)
AINC-: JP10.3 JP12.2(S2) LKC.8 R56.2(N2)
AIND+: JP13.1 JP15.2(S2) LKD.2 R74.2(N2)
AIND-: JP14.3 JP16.2(S2) LKD.8 R69.2(N2)
BIA+: JP1.1 R9.1
BIA-: JP2.3 R11.1
BIB+: JP5.1 R38.1
BIB-: JP6.3 R39.1
BIC+: JP9.3 R50.1
BIC-: JP10.1 R55.1
BID+: JP13.3 R66.1
BID-: JP14.1 R67.1
BOA+: A1.1 C20.2(N2) C24.2(N2) JP3.1 R36.2(N2)
BOA-: A1.7 C21.2(N2) C25.2(N2) JP4.1 R37.2(N2)
BOB+: A2.1 C33.2(N2) C37.2(N2) JP7.1 R48.2(N2)
BOB-: A2.7 C34.2(N2) C38.2(N2) JP8.1 R49.2(N2)
BOC+: A3.1 C43.2(N2) C47.2(N2) JP11.1 R64.2(N2)
BOC-: A3.7 C44.2(N2) C48.2(N2) JP12.1 R65.2(N2)
BOD+: A4.1 C53.2(N2) C57.2(N2) JP15.1 R79.2(N2)
BOD-: A4.7 C54.2(N2) C58.2(N2) JP16.1 R80.2(N2)
CSN: R16.1 R24.1 U1.H9
ENABLE: ENABLE.2 U1.E2
GA0: P1.C34 U4.2
GA1: P1.D35 U4.1
IN_LDO: IN_LDO.1(N1) J3.5 U1.C5 U1.C6 U1.D5
INA+: A+.1(N1) INA+.1 JP1.2(COM) R1.2(N2) R70.1
INA-: A-.1(N1) INA-.1 JP2.2(COM) R2.2(N2) R71.1
INB+: B+.1(N1) INB+.1 JP5.2(COM) R3.2(N2) R43.1
INB-: B-.1(N1) INB-.1 JP6.2(COM) R4.2(N2) R40.1
INC+: C+.1(N1) INC+.1 JP9.2(COM) R5.2(N2) R59.1
INC-: C-.1(N1) INC-.1 JP10.2(COM) R6.2(N2) R56.1
IND+: D+.1(N1) IND+.1 JP13.2(COM) R7.2(N2) R74.1
IND-: D-.1(N1) IND-.1 JP14.2(COM) R8.2(N2) R69.1
OUT_LDO: J2.1 OUT_LDO.1(N1) P3.1 U1.D6 U1.D7
OUTA+: C2.2(N2) LKA.11 U1.H7
OUTA-: C1.2(N2) LKA.9 U1.H6
OUTB+: C4.2(N2) LKB.11 U1.H3
OUTB-: C3.2(N2) LKB.9 U1.H2
OUTC+: C6.2(N2) LKC.12(N6) U1.B3
OUTC-: C5.2(N2) LKC.10 U1.B2
OUTD+: C8.2(N2) LKD.12(N6) U1.B7
OUTD-: C7.2(N2) LKD.10 U1.B6
PMODE: MODE.2 U1.E3
R1A+: LKA.3 LKA.10 U1.J6
R1A-: LKA.5 LKA.12(N6) U1.J7
R1B+: LKB.3 LKB.10 U1.J2
R1B-: LKB.5 LKB.12(N6) U1.J3
R1C+: LKC.4 LKC.9 U1.A2
R1C-: LKC.6 LKC.11 U1.A3
R1D+: LKD.4 LKD.9 U1.A6
R1D-: LKD.6 LKD.11 U1.A7
R2A+: LKA.2 LKA.4 U1.J4
R2A-: LKA.6 LKA.8 U1.J5
R2B+: LKB.2 LKB.4 U1.F1
R2B-: LKB.6 LKB.8 U1.G1
R2C+: LKC.1 LKC.3 U1.D1
R2C-: LKC.5 LKC.7 U1.C1
R2D+: LKD.1 LKD.3 U1.A4
R2D-: LKD.5 LKD.7 U1.A5
REFSNS: R81.2(N2) REFS.1(N1)
SCL: P1.C30 U4.6
SCLK: R15.1 R23.1 R27.1 U1.D9
SCLK_R: P1.H4 R23.2(N2)
SDA: P1.C31 U4.5
SDI: R19.1 R25.1 U1.E9
SDOA: R13.1 R26.1 U1.G9
SDOB: R14.1 R28.2(N2) U1.F9
SDOC: R20.1 R29.2(N2) U1.C9
SDOD: R17.1 R68.2(N2) U1.B9
SJA+: C1.1 U1.H4
SJA-: C2.1 U1.H5
SJB+: C3.1 U1.F2
SJB-: C4.1 U1.G2
SJC+: C5.1 U1.D2
SJC-: C6.1 U1.C2
SJD+: C7.1 U1.B4
SJD-: C8.1 U1.B5
UNNAMED_2_ADAQ43804_I54_DNC4: R81.1 U1.G6
UNNAMED_3_CN12PV3_I71_P1: P2.1 R24.2(N2)
UNNAMED_3_CN12PV3_I71_P2: P2.2 R25.2(N2)
UNNAMED_3_CN12PV3_I71_P3: P2.3 R26.2(N2)
UNNAMED_3_CN12PV3_I71_P4: P2.4 R27.2(N2)
UNNAMED_3_CN12PV3_I71_P7: P2.7 R28.1
UNNAMED_3_CN12PV3_I71_P8: P2.8 R29.1
UNNAMED_3_CN12PV3_I71_P9: P2.9 R68.1
UNNAMED_3_CN160PCDGH_I25_N8: P1.D8 R13.2(N2)
UNNAMED_3_CN160PCDGH_I25_N9: P1.D9 R14.2(N2)
UNNAMED_3_CN160PCDGH_I25_N30: P1.D30 P1.D31
UNNAMED_3_CN160PCDGH_I35_N6: P1.G6 R15.2(N2)
UNNAMED_3_CN160PCDGH_I35_N7: P1.G7 R16.2(N2)
UNNAMED_3_CN160PCDGH_I35_N9: P1.G9 R17.2(N2)
UNNAMED_3_CN160PCDGH_I38_N7: P1.H7 R19.2(N2)
UNNAMED_3_CN160PCDGH_I38_N8: P1.H8 R20.2(N2)
UNNAMED_4_ADP7142_I61_EN: C13.1 R33.2(N2) U3.4 U3.6 UNK+6V.1
UNNAMED_4_ADP7142_I61_SENSE: C15.1 R54.1 U3.1(VOUT) U3.2
UNNAMED_4_ADP7142_I61_SS: C14.2(N2) U3.5
UNNAMED_4_CAP_I16_N1: C10.1 E1.1 L1.1 R34.2(N2) U2.1 U2.2(VIN) UNK3V3.1
UNNAMED_4_CAP_I18_N2: C11.2(N2) U2.8
UNNAMED_4_CAP_I37_N2: C27.2(N2) R52.2(N2)
UNNAMED_4_CAP_I41_N1: C26.1 U2.3
UNNAMED_4_CAP_I45_N1: C28.1 R31.2(N2) R32.1 U2.6
UNNAMED_4_CAP_I45_N2: C12.1 C28.2(N2) D1.C R31.1 R33.1
UNNAMED_4_CN3P_I47_N3: J2.3(N3) R10.2(N2)
UNNAMED_4_DIOLED_I6_P: DS1.A(P) R34.1
UNNAMED_4_DIOSCHOTTKY_I56_P: D1.A(P) L1.2(N2) U2.10
UNNAMED_4_FERRITE_I62_N2: E1.2(N2) R53.2(N2)
UNNAMED_4_ICLT8362_I19_RT: R51.1 U2.7
UNNAMED_4_ICLT8362_I19_VC: R52.1 U2.5
UNNAMED_6_ADA46252V2_I193_: A1.5 C19.1 R22.2(N2)
UNNAMED_6_ADA46252V2_I193__1: A1.6 C25.1 R35.2(N2) R37.1
UNNAMED_6_ADA46252V2_I194_: A1.2 C24.1 R30.2(N2) R36.1
UNNAMED_6_ADA46252V2_I194__1: A1.3 C18.1 R21.2(N2)
UNNAMED_6_ADA46252V2_I198_: A2.5 C32.1 R45.2(N2)
UNNAMED_6_ADA46252V2_I198__1: A2.6 C38.1 R47.2(N2) R49.1
UNNAMED_6_ADA46252V2_I199_: A2.3 C31.1 R44.2(N2)
UNNAMED_6_ADA46252V2_I199__1: A2.2 C37.1 R46.2(N2) R48.1
UNNAMED_6_ADA46252V2_I202_: A3.3 C41.1 R60.2(N2)
UNNAMED_6_ADA46252V2_I202__1: A3.2 C47.1 R62.2(N2) R64.1
UNNAMED_6_ADA46252V2_I203_: A3.5 C42.1 R61.2(N2)
UNNAMED_6_ADA46252V2_I203__1: A3.6 C48.1 R63.2(N2) R65.1
UNNAMED_6_ADA46252V2_I205_: A4.3 C51.1 R75.2(N2)
UNNAMED_6_ADA46252V2_I205__1: A4.2 C57.1 R77.2(N2) R79.1
UNNAMED_6_ADA46252V2_I206_: A4.6 C58.1 R78.2(N2) R80.1
UNNAMED_6_ADA46252V2_I206__1: A4.5 C52.1 R76.2(N2)
UNNAMED_6_CAP_I59_N1: C20.1 R12.2(N2) R21.1
UNNAMED_6_CAP_I62_N1: C16.1 R9.2(N2) R12.1
UNNAMED_6_CAP_I66_N1: C17.1 R11.2(N2) R18.1
UNNAMED_6_CAP_I72_N1: C21.1 R18.2(N2) R22.1
UNNAMED_6_CAP_I84_N1: C33.1 R41.2(N2) R44.1
UNNAMED_6_CAP_I92_N1: C29.1 R38.2(N2) R41.1
UNNAMED_6_CAP_I94_N1: C34.1 R42.2(N2) R45.1
UNNAMED_6_CAP_I103_N1: C30.1 R39.2(N2) R42.1
UNNAMED_6_CAP_I124_N1: C43.1 R57.2(N2) R60.1
UNNAMED_6_CAP_I132_N1: C39.1 R50.2(N2) R57.1
UNNAMED_6_CAP_I134_N1: C44.1 R58.2(N2) R61.1
UNNAMED_6_CAP_I140_N1: C40.1 R55.2(N2) R58.1
UNNAMED_6_CAP_I162_N1: C53.1 R72.2(N2) R75.1
UNNAMED_6_CAP_I169_N1: C54.1 R73.2(N2) R76.1
UNNAMED_6_CAP_I182_N1: C49.1 R66.2(N2) R72.1
UNNAMED_6_CAP_I187_N1: C50.1 R67.2(N2) R73.1
VLOGIC: J2.2 U1.C8 VLOGIC.1(N1)
VNEG: A1.4(V-) A2.4(V-) A3.4(V-) A4.4(V-) C23.1 C36.1 C46.1 C56.1 C60.1 VNEG.1(N1)
VPOS: A1.8 A2.8 A3.8 A4.8 C22.1 C35.1 C45.1 C55.1 C59.1 VPOS.1(N1)
VS+: ENABLE.1 J3.1 MODE.1 U1.C3 U1.C4 U1.D3 U1.D4 U1.F7 VS+.1(N1)
VS-: J3.3 U1.F3 U1.F4 U1.G3 U1.G4(VS-_4) VS-.1(N1)

Pads without a net: P1 C2 C3 C6 C7 C10 C11 C14 C15 C18 C19 C22 C23 C26 C27 C35 C37 D1 D4 D5 D11 D12 D14 D15 D17 D18 D20 D21 D23 D24 D26 D27 D29 D33 D34 G2 G3 G10 G12 G13 G15 G16 G18 G19 G21 G22 G24 G25 G27 G28 G30 G31 G33 G34 G36 G37 G39 H1 H5 H10 H11 H13 H14 H16 H17 H19 H20 H22 H23 H25 H26 H28 H29 H31 H32 H34 H35 H37 H38 H40; P2 10; U1 E6 F5 F6 G7

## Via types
v1: diameter 0.508, hole 0.254, TOP to BOTTOM, 430 vias
v2: diameter 0.406, hole 0.203, TOP to BOTTOM, 48 vias

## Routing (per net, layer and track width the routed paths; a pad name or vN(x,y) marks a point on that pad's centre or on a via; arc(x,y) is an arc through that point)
3V3IN: length 2.3
  BOTTOM w1.016: J1.2 57.37,64.46
  vias: v1(43.56,66.93)
+3V3_FMC: length 3.6
  BOTTOM w0.508: 71.75,7.56 v1(71.12,8.19) ; 73.03,6.29 v1(73.66,6.92) ; 71.75,5.02 v1(71.12,5.65) ; 71.75,10.1 v1(71.12,9.46)
+3V3_PMOD: length 13.2
  TOP w0.508: J1.3 R10.1
  BOTTOM w0.508: 70.23,74.17 P2.6 ; P2.6 71.31,75.25 ; P2.6 72.39,74.17 ; P2.6 71.31,73.09 ; 73.85,73.09 P2.12 ; P2.12 74.93,74.17 ; P2.12 72.77,74.17 ; P2.12 73.85,75.25 ; J1.3 59.69,66.49 ; J1.3 58.8,65.73 ; J1.3 60.58,65.73
AGND: length 661.1
  TOP w0.254: U2.9 50.13,65.71 U2.PAD
  TOP w0.508: INB-.3 11.2,24.43 ; INB-.3 9.84,23.08 ; INB-.3 8.48,24.43 ; INB-.3 9.84,25.79 ; INB+.4 11.2,29.84 ; INB+.4 9.84,31.2 ; INB+.4 8.48,29.84 ; INB+.4 9.84,28.49 ; 3.4,47.62 INC+.2 ; INC+.2 6.12,47.62 ; INC+.2 4.76,46.27 ; INC+.2 4.76,48.98 ; P2.5 71.31,72.71 ; P2.5 72.39,71.63 ; P2.5 71.31,70.55 ; P2.5 70.23,71.63 ; 20.36,70.08 IND+.2 ; IND+.2 19,71.44 ; IND+.2 20.36,72.8 ; IND+.2 21.72,71.44 ; INB+.5 6.12,29.84 ; INB+.5 4.76,28.49 ; INB+.5 3.4,29.84 ; INB+.5 4.76,31.2 ; INA+.5 19.98,7.01 ; INA+.5 18.62,5.65 ; INA+.5 21.34,5.65 ; INA+.5 19.98,4.29 ; INA-.2 31.83,10.73 ; INA-.2 29.11,10.73 ; INA-.2 30.47,12.09 ; INA-.2 30.47,9.37 ; 34.19,10.73 INA-.3 ; INA-.3 35.55,12.09 ; INA-.3 36.91,10.73 ; INA-.3 35.55,9.37 ; 8.48,19.35 INB-.4 ; INB-.4 9.84,20.71 ; INB-.4 11.2,19.35 ; INB-.4 9.84,18 ; IND-.3 35.93,72.8 ; IND-.3 35.93,70.08 ; IND-.3 37.29,71.44 ; IND-.3 34.57,71.44 ; C9.2 66.62,18.72 ; C9.2 65.46,18.72 ; C9.2 v1(66.04,19.62) ; 30.47,4.29 INA-.5 ; INA-.5 31.83,5.65 ; INA-.5 30.47,7.01 ; INA-.5 29.11,5.65 ; GND1.1 56.86,55.05 ; GND1.1 55.84,56.07 ; GND1.1 54.82,55.05 ; 58.77,34.18 GND2.1 ; GND2.1 59.79,33.16 ; GND2.1 60.8,34.18 ; GND2.1 59.79,35.19 ; 35.55,4.29 INA-.4 ; INA-.4 36.91,5.65 ; INA-.4 35.55,7.01 ; INA-.4 34.19,5.65 ; 8.48,42.55 INC+.4 ; INC+.4 9.84,41.19 ; INC+.4 9.84,43.9 ; INC+.4 11.2,42.55 ; 19.98,9.37 INA+.2 ; INA+.2 18.62,10.73 ; INA+.2 19.98,12.09 ; INA+.2 21.34,10.73 ; INC+.3 11.2,47.62 ; INC+.3 9.84,46.27 ; INC+.3 9.84,48.98 ; INC+.3 8.48,47.62 ; IND+.4 26.8,66.36 ; IND+.4 25.44,67.72 ; IND+.4 24.08,66.36 ; IND+.4 25.44,65 ; ENABLE.3 50.86,30.24 ; ENABLE.3 50.86,28.46 ; ENABLE.3 50.1,29.35 ; INB-.2 6.12,24.43 ; INB-.2 3.4,24.43 ; INB-.2 4.76,25.79 ; INB-.2 4.76,23.08 ; INB+.3 11.2,34.92 ; INB+.3 9.84,33.57 ; INB+.3 9.84,36.28 ; INB+.3 8.48,34.92 ; IND+.3 25.44,72.8 ; IND+.3 24.08,71.44 ; IND+.3 26.8,71.44 ; IND+.3 25.44,70.08 ; INC-.2 6.12,58.12 ; INC-.2 4.76,59.47 ; INC-.2 4.76,56.76 ; INC-.2 3.4,58.12 ; IND-.2 30.85,72.8 ; IND-.2 30.85,70.08 ; IND-.2 32.21,71.44 ; IND-.2 29.49,71.44 ; GND5.1 7.3,67.37 ; GND5.1 8.32,66.36 ; GND5.1 7.3,65.34 ; GND5.1 6.29,66.36 ; GND3.1 8.32,10.73 ; GND3.1 6.29,10.73 ; GND3.1 7.3,9.71 ; GND3.1 7.3,11.75 ; 9.84,51.68 INC-.4 ; INC-.4 11.2,53.04 ; INC-.4 8.48,53.04 ; INC-.4 9.84,54.39 ; INC-.3 9.84,59.47 ; INC-.3 8.48,58.12 ; INC-.3 9.84,56.76 ; INC-.3 11.2,58.12 ; IND-.4 35.93,67.72 ; IND-.4 37.29,66.36 ; IND-.4 35.93,65 ; IND-.4 34.57,66.36 ; 25.06,9.37 INA+.3 ; INA+.3 23.7,10.73 ; INA+.3 26.42,10.73 ; INA+.3 25.06,12.09 ; 72.77,71.63 P2.11 ; P2.11 73.85,70.55 ; P2.11 74.93,71.63 ; P2.11 73.85,72.71 ; 3.4,42.55 INC+.5 ; INC+.5 4.76,43.9 ; INC+.5 4.76,41.19 ; INC+.5 6.12,42.55 ; INA+.4 26.42,5.65 ; INA+.4 25.06,4.29 ; INA+.4 23.7,5.65 ; INA+.4 25.06,7.01 ; GND4.1 47.18,8.03 ; GND4.1 48.2,7.02 ; GND4.1 47.18,6 ; GND4.1 46.16,7.02 ; 4.76,51.68 INC-.5 ; INC-.5 4.76,54.39 ; INC-.5 6.12,53.04 ; INC-.5 3.4,53.04 ; C11.1 54.51,65.47 v1(54.77,65.21) ; IND+.5 21.72,66.36 ; IND+.5 20.36,67.72 ; IND+.5 19,66.36 ; IND+.5 20.36,65 ; IND-.5 30.85,67.72 ; IND-.5 29.49,66.36 ; IND-.5 30.85,65 ; IND-.5 32.21,66.36 ; INB+.2 6.12,34.92 ; INB+.2 4.76,33.57 ; INB+.2 3.4,34.92 ; INB+.2 4.76,36.28 ; 3.4,19.35 INB-.5 ; INB-.5 4.76,18 ; INB-.5 6.12,19.35 ; INB-.5 4.76,20.71 ; 50.86,31.48 MODE.3 ; MODE.3 50.1,32.37 ; MODE.3 50.86,33.26 ; C14.1 v1(54.29,57.15)
  L2_GND w0.508: INA+.2 19.98,12.09 ; INA+.2 19.98,9.37 ; INA+.2 21.34,10.73 ; INA+.2 18.62,10.73 ; 50.1,32.37 MODE.3 ; MODE.3 50.86,33.26 ; MODE.3 50.86,31.48 ; IND-.3 37.29,71.44 ; IND-.3 35.93,72.8 ; IND-.3 35.93,70.08 ; IND-.3 34.57,71.44 ; 8.48,29.84 INB+.4 ; INB+.4 9.84,31.2 ; INB+.4 11.2,29.84 ; INB+.4 9.84,28.49 ; INC-.3 11.2,58.12 ; INC-.3 9.84,56.76 ; INC-.3 8.48,58.12 ; INC-.3 9.84,59.47 ; IND-.5 32.21,66.36 ; IND-.5 30.85,67.72 ; IND-.5 30.85,65 ; IND-.5 29.49,66.36 ; 58.77,34.18 GND2.1 ; GND2.1 59.79,35.19 ; GND2.1 60.8,34.18 ; GND2.1 59.79,33.16 ; 3.4,58.12 INC-.2 ; INC-.2 4.76,59.47 ; INC-.2 4.76,56.76 ; INC-.2 6.12,58.12 ; 3.4,29.84 INB+.5 ; INB+.5 4.76,31.2 ; INB+.5 6.12,29.84 ; INB+.5 4.76,28.49 ; IND+.2 21.72,71.44 ; IND+.2 20.36,72.8 ; IND+.2 20.36,70.08 ; IND+.2 19,71.44 ; 9.84,51.68 INC-.4 ; INC-.4 11.2,53.04 ; INC-.4 8.48,53.04 ; INC-.4 9.84,54.39 ; 4.76,33.57 INB+.2 ; INB+.2 4.76,36.28 ; INB+.2 3.4,34.92 ; INB+.2 6.12,34.92 ; INA+.3 26.42,10.73 ; INA+.3 25.06,9.37 ; INA+.3 25.06,12.09 ; INA+.3 23.7,10.73 ; J3.4 42.29,55.75 ; INA-.4 35.55,7.01 ; INA-.4 36.91,5.65 ; INA-.4 35.55,4.29 ; INA-.4 34.19,5.65 ; 30.47,4.29 INA-.5 ; INA-.5 30.47,7.01 ; INA-.5 31.83,5.65 ; INA-.5 29.11,5.65 ; 3.4,42.55 INC+.5 ; INC+.5 4.76,41.19 ; INC+.5 4.76,43.9 ; INC+.5 6.12,42.55 ; 25.06,4.29 INA+.4 ; INA+.4 26.42,5.65 ; INA+.4 23.7,5.65 ; INA+.4 25.06,7.01 ; 20.36,65 IND+.5 ; IND+.5 21.72,66.36 ; IND+.5 19,66.36 ; IND+.5 20.36,67.72 ; IND-.4 35.93,67.72 ; IND-.4 37.29,66.36 ; IND-.4 35.93,65 ; IND-.4 34.57,66.36 ; 4.76,23.08 INB-.2 ; INB-.2 4.76,25.79 ; INB-.2 6.12,24.43 ; INB-.2 3.4,24.43 ; INA-.2 31.83,10.73 ; INA-.2 30.47,9.37 ; INA-.2 30.47,12.09 ; INA-.2 29.11,10.73 ; GND1.1 56.86,55.05 ; GND1.1 55.84,54.04 ; GND1.1 55.84,56.07 ; GND1.1 54.82,55.05 ; 8.48,19.35 INB-.4 ; INB-.4 11.2,19.35 ; INB-.4 9.84,18 ; INB-.4 9.84,20.71 ; GND3.1 8.32,10.73 ; GND3.1 7.3,11.75 ; GND3.1 7.3,9.71 ; GND3.1 6.29,10.73 ; 19.98,4.29 INA+.5 ; INA+.5 18.62,5.65 ; INA+.5 21.34,5.65 ; INA+.5 19.98,7.01 ; 25.44,70.08 IND+.3 ; IND+.3 26.8,71.44 ; IND+.3 25.44,72.8 ; IND+.3 24.08,71.44 ; INB-.5 4.76,20.71 ; INB-.5 4.76,18 ; INB-.5 6.12,19.35 ; INB-.5 3.4,19.35 ; GND4.1 47.18,8.03 ; GND4.1 47.18,6 ; GND4.1 48.2,7.02 ; GND4.1 46.16,7.02 ; 70.23,71.63 P2.5 ; P2.5 71.31,72.71 ; P2.5 71.31,70.55 ; P2.5 72.39,71.63 ; INC+.3 11.2,47.62 ; INC+.3 8.48,47.62 ; INC+.3 9.84,46.27 ; INC+.3 9.84,48.98 ; GND5.1 8.32,66.36 ; GND5.1 7.3,65.34 ; GND5.1 7.3,67.37 ; GND5.1 6.29,66.36 ; 9.84,41.19 INC+.4 ; INC+.4 11.2,42.55 ; INC+.4 8.48,42.55 ; INC+.4 9.84,43.9 ; INA-.3 36.91,10.73 ; INA-.3 35.55,12.09 ; INA-.3 35.55,9.37 ; INA-.3 34.19,10.73 ; 3.4,47.62 INC+.2 ; INC+.2 6.12,47.62 ; INC+.2 4.76,48.98 ; INC+.2 4.76,46.27 ; 25.44,65 IND+.4 ; IND+.4 26.8,66.36 ; IND+.4 25.44,67.72 ; IND+.4 24.08,66.36 ; INB+.3 11.2,34.92 ; INB+.3 9.84,33.57 ; INB+.3 8.48,34.92 ; INB+.3 9.84,36.28 ; P2.11 73.85,72.71 ; P2.11 73.85,70.55 ; P2.11 74.93,71.63 ; P2.11 72.77,71.63 ; IND-.2 30.85,72.8 ; IND-.2 30.85,70.08 ; IND-.2 29.49,71.44 ; IND-.2 32.21,71.44 ; INB-.3 9.84,25.79 ; INB-.3 8.48,24.43 ; INB-.3 9.84,23.08 ; INB-.3 11.2,24.43 ; 50.1,29.35 ENABLE.3 ; ENABLE.3 50.86,28.46 ; ENABLE.3 50.86,30.24 ; 4.76,51.68 INC-.5 ; INC-.5 3.4,53.04 ; INC-.5 4.76,54.39 ; INC-.5 6.12,53.04
  BOTTOM w0.508: 24.48,61.41 C56.2 ; C56.2 23.93,61.99 ; C56.2 24.48,62.58 ; C18.2 23.23,21.24 ; C18.2 22.64,20.69 ; C18.2 23.81,20.69 ; INC+.2 6.12,47.62 ; INC+.2 3.4,47.62 ; INC+.2 4.76,46.27 ; INC+.2 4.76,48.98 ; v1(17.64,46.38) 17.64,45.89 R62.1 ; GND2.1 59.79,35.19 ; GND2.1 59.79,33.16 ; GND2.1 60.8,34.18 ; GND2.1 58.77,34.18 ; v1(24.19,58.56) 23.71,58.56 R77.1 ; 4.76,18 INB-.5 ; INB-.5 3.4,19.35 ; INB-.5 6.12,19.35 ; INB-.5 4.76,20.71 ; v1(34.05,61.87) 34.24,62.06 C50.2 ; INA+.4 25.06,7.01 ; INA+.4 25.06,4.29 ; INA+.4 23.7,5.65 ; INA+.4 26.42,5.65 ; INC-.5 6.12,53.04 ; INC-.5 3.4,53.04 ; INC-.5 4.76,54.39 ; INC-.5 4.76,51.68 ; INC-.2 6.12,58.12 ; INC-.2 4.76,56.76 ; INC-.2 4.76,59.47 ; INC-.2 3.4,58.12 ; INA+.2 21.34,10.73 ; INA+.2 18.62,10.73 ; INA+.2 19.98,9.37 ; INA+.2 19.98,12.09 ; 4.76,28.49 INB+.5 ; INB+.5 4.76,31.2 ; INB+.5 6.12,29.84 ; INB+.5 3.4,29.84 ; 19.8,31.09 C31.2 ; C31.2 20.35,31.67 ; C31.2 19.8,32.26 ; 6.29,10.73 GND3.1 ; GND3.1 7.3,11.75 ; GND3.1 7.3,9.71 ; GND3.1 8.32,10.73 ; P2.11 74.93,71.63 ; P2.11 73.85,70.55 ; P2.11 72.77,71.63 ; R30.1 23.32,18.53 v1(23.81,18.53) ; 30.47,4.29 INA-.5 ; INA-.5 29.11,5.65 ; INA-.5 30.47,7.01 ; INA-.5 31.83,5.65 ; INB-.3 11.2,24.43 ; INB-.3 8.48,24.43 ; INB-.3 9.84,23.08 ; INB-.3 9.84,25.79 ; 20.36,65 IND+.5 ; IND+.5 19,66.36 ; IND+.5 20.36,67.72 ; IND+.5 21.72,66.36 ; INA-.2 31.83,10.73 ; INA-.2 29.11,10.73 ; INA-.2 30.47,12.09 ; INA-.2 30.47,9.37 ; INB+.3 11.2,34.92 ; INB+.3 9.84,36.28 ; INB+.3 9.84,33.57 ; INB+.3 8.48,34.92 ; 9.84,18 INB-.4 ; INB-.4 11.2,19.35 ; INB-.4 9.84,20.71 ; INB-.4 8.48,19.35 ; 50.1,32.37 MODE.3 50.86,33.26 ; 4.76,33.57 INB+.2 ; INB+.2 3.4,34.92 ; INB+.2 4.76,36.28 ; INB+.2 6.12,34.92 ; 18.62,5.65 INA+.5 ; INA+.5 21.34,5.65 ; INA+.5 19.98,4.29 ; INA+.5 19.98,7.01 ; IND-.4 35.93,67.72 ; IND-.4 37.29,66.36 ; IND-.4 34.57,66.36 ; 8.48,29.84 INB+.4 ; INB+.4 11.2,29.84 ; INB+.4 9.84,31.2 ; INB+.4 9.84,28.49 ; C30.2 v1(15.11,18.47) ; 23.02,60.73 C51.2 ; C51.2 23.61,61.27 ; C51.2 24.19,60.73 ; 47.18,6 GND4.1 ; GND4.1 48.2,7.02 ; GND4.1 46.16,7.02 ; GND4.1 47.18,8.03 ; 70.23,71.63 P2.5 ; P2.5 71.31,70.55 ; P2.5 72.39,71.63 ; GND1.1 55.84,56.07 ; GND1.1 56.86,55.05 ; GND1.1 55.84,54.04 ; GND1.1 54.82,55.05 ; 50.1,29.35 ENABLE.3 50.86,28.46 ; 8.48,58.12 INC-.3 ; INC-.3 9.84,59.47 ; INC-.3 9.84,56.76 ; 8.48,42.55 INC+.4 ; INC+.4 11.2,42.55 ; INC+.4 9.84,41.19 ; INC+.4 9.84,43.9 ; INC+.5 6.12,42.55 ; INC+.5 4.76,41.19 ; INC+.5 4.76,43.9 ; INC+.5 3.4,42.55 ; IND-.5 32.21,66.36 ; IND-.5 29.49,66.36 ; IND-.5 30.85,67.72 ; INC+.3 9.84,48.98 ; INC+.3 9.84,46.27 ; INC+.3 8.48,47.62 ; INC+.3 11.2,47.62 ; 14.73,36.53 C29.2 14.19,35.94 ; C45.2 22.56,53 ; C45.2 22.02,53.58 ; C45.2 22.02,52.41 ; IND-.3 37.29,71.44 ; IND-.3 34.57,71.44 ; IND-.3 35.93,72.8 ; IND-.3 35.93,70.08 ; 30.81,53.64 C55.2 ; C55.2 30.23,54.18 ; C55.2 31.39,54.18 ; 25.44,70.08 IND+.3 ; IND+.3 24.08,71.44 ; IND+.3 25.44,72.8 ; IND+.3 26.8,71.44 ; C42.2 14.2,55.45 ; C42.2 13.66,54.86 ; C42.2 14.2,54.28 ; 25.44,65 IND+.4 ; IND+.4 24.08,66.36 ; IND+.4 25.44,67.72 ; IND+.4 26.8,66.36 ; 9.84,51.68 INC-.4 ; INC-.4 8.48,53.04 ; INC-.4 9.84,54.39 ; 22.02,29.22 C36.2 ; C36.2 22.56,29.81 ; C36.2 22.02,30.39 ; 23.7,10.73 INA+.3 ; INA+.3 26.42,10.73 ; INA+.3 25.06,9.37 ; INA+.3 25.06,12.09 ; 33.3,16.04 C22.2 33.84,16.62 ; INA-.4 35.55,7.01 ; INA-.4 34.19,5.65 ; INA-.4 35.55,4.29 ; INA-.4 36.91,5.65 ; C41.2 15.47,46.38 ; C41.2 15.47,45.21 ; C41.2 14.93,45.8 ; 34.19,10.73 INA-.3 ; INA-.3 35.55,9.37 ; INA-.3 35.55,12.09 ; INA-.3 36.91,10.73 ; C46.2 14.79,46.66 ; C46.2 14.21,46.12 ; C46.2 13.62,46.66 ; INB-.2 6.12,24.43 ; INB-.2 4.76,25.79 ; INB-.2 4.76,23.08 ; INB-.2 3.4,24.43 ; 37.02,16.89 C17.2 36.44,16.34 ; v1(31.74,19.72) 32.12,19.72 R35.1 ; C23.2 25.68,22.91 ; C23.2 24.51,22.91 ; C23.2 25.1,23.45 ; v1(32.09,59.83) 32.58,59.83 R78.1 ; v1(16.37,54.28) 16.37,54.77 R63.1 ; C52.2 32.68,62.54 ; C52.2 33.26,62 ; C52.2 32.09,62 ; 20.36,70.08 IND+.2 ; IND+.2 21.72,71.44 ; IND+.2 19,71.44 ; IND+.2 20.36,72.8 ; 18.38,15.62 C16.2 18.96,15.07 ; GND5.1 7.3,67.37 ; GND5.1 7.3,65.34 ; GND5.1 6.29,66.36 ; GND5.1 8.32,66.36 ; C39.2 v1(15.41,44.36) ; 21.07,22.02 C32.2 ; C32.2 21.62,22.61 ; C32.2 21.07,23.19 ; C40.2 14.14,56.43 v1(14.33,56.24) ; 15.15,21.61 C35.2 15.73,21.06 ; C19.2 32.3,22.51 ; C19.2 32.88,21.96 ; C19.2 31.71,21.96 ; v1(18.91,23.19) 18.91,22.7 R47.1 ; 30.85,70.08 IND-.2 ; IND-.2 29.49,71.44 ; IND-.2 32.21,71.44 ; IND-.2 30.85,72.8 ; v1(17.64,31.09) 17.64,31.58 R46.1 ; C49.2 v1(22.17,60.79) ; J3.4 42.29,55.75
  vias: v1(1.27,69.91) v1(1.27,64.83) v1(1.27,59.75) v1(1.27,54.42) v1(1.27,49.59) v1(1.27,44.01) v1(1.27,39.43) v1(1.27,34.35) v1(1.27,29.27) v1(1.27,24.19) v1(1.27,19.11) v1(1.27,14.03) v1(1.27,8.95) v1(3.81,67.37) v1(3.81,62.29) v1(3.81,36.89) v1(3.81,31.81) v1(3.81,26.73) v1(3.81,21.27) v1(3.81,16.57) v1(3.81,11.49) v1(6.35,74.99) v1(6.35,69.91) v1(6.35,64.83) v1(6.35,59.75) v1(6.35,49.59) v1(6.35,39.43) v1(6.35,34.35) v1(6.35,29.27) v1(6.35,14.03) v1(6.35,8.95) v1(8.89,67.37) v1(8.89,62.29) v1(8.89,36.89) v1(8.89,26.73) v1(8.89,16.57) v1(8.89,11.49) v1(8.89,6.41) v1(8.89,1.33) v1(11.43,74.99) v1(11.43,69.91) v1(11.43,64.83) v1(11.43,59.75) v1(11.43,49.59) v1(11.43,39.43) v1(11.43,29.27) v1(11.43,24.19) v1(11.43,14.03) v1(11.43,8.95) v1(11.43,3.87) v1(12.64,60.09) v1(13.53,41.35) v1(13.53,36.12) v1(13.53,18.16) v1(13.97,72.45) v1(13.97,67.37) v1(13.97,62.29) v1(13.97,11.49) v1(13.97,6.41) v1(13.97,1.33) v1(14.2,53.98) v1(14.21,45.9) v1(14.73,36.83) v1(14.97,21.61) v1(15.47,45.03) v1(16.51,74.99) v1(16.51,69.91) v1(16.51,64.83) v1(16.51,8.95) v1(16.51,3.87) v1(16.75,51.22) v1(16.75,26.25) v1(17.64,51.22) v1(17.64,50.33) v1(17.64,27.14) v1(17.64,26.25) v1(18.07,15.62) v1(18.53,51.22) v1(18.53,50.33) v1(18.53,49.44) v1(18.53,28.03) v1(18.53,27.14) v1(18.53,26.25) v1(18.78,12.64) v1(19.05,67.37) v1(19.05,57.21) v1(19.05,36.89) v1(19.05,1.33) v1(19.16,64.45) v1(19.8,32.56) v1(21.59,74.99) v1(21.59,69.91) v1(21.59,54.67) v1(21.59,49.59) v1(21.59,39.43) v1(21.59,24.19) v1(21.59,3.87) v1(21.96,22.61) v1(22.34,20.69) v1(22.85,60.73) v1(22.91,53) v1(22.91,29.81) v1(23.71,61.99) v1(24.13,72.45) v1(24.13,67.37) v1(24.13,52.13) v1(24.13,47.05) v1(24.13,36.89) v1(24.13,31.81) v1(24.13,26.73) v1(24.13,1.33) v1(25.1,23.79) v1(26.67,74.99) v1(26.67,69.91) v1(26.67,64.83) v1(26.67,54.67) v1(26.67,49.59) v1(26.67,29.27) v1(26.67,24.19) v1(26.67,8.95) v1(26.67,3.87) v1(26.87,19.42) v1(26.87,18.53) v1(26.87,17.64) v1(27.25,59.45) v1(27.25,58.56) v1(27.25,57.67) v1(27.76,19.42) v1(27.76,18.53) v1(28.14,58.56) v1(28.14,57.67) v1(28.65,19.42) v1(29.03,57.67) v1(29.21,72.45) v1(29.21,67.37) v1(29.21,52.13) v1(29.21,47.05) v1(29.21,26.73) v1(29.21,21.65) v1(29.21,1.33) v1(30.81,53.29) v1(31.75,74.99) v1(31.75,69.91) v1(31.75,49.59) v1(31.75,29.27) v1(31.75,24.19) v1(31.75,8.95) v1(31.75,3.87) v1(31.79,62) v1(32.3,22.85) v1(33.3,15.86) v1(34.29,72.45) v1(34.29,67.37) v1(34.29,52.13) v1(34.29,1.33) v1(36.44,16) v1(36.74,12.64) v1(36.83,74.99) v1(36.83,69.91) v1(36.83,64.83) v1(36.83,8.95) v1(36.83,3.87) v1(37.9,63.56) v1(38.27,3.16) v1(38.27,2.4) v1(38.27,1.64) v1(39.37,52.13) v1(39.37,21.65) v1(39.37,16.57) v1(39.37,11.49) v1(41.91,59.75) v1(41.91,49.59) v1(41.91,44.51) v1(41.91,29.27) v1(41.91,24.19) v1(41.91,19.11) v1(41.91,14.03) v1(41.91,8.95) v1(42.45,68.08) v1(42.37,64.83) v1(42.61,73.05) v1(44.45,57.21) v1(44.45,26.73) v1(44.45,21.65) v1(44.45,16.57) v1(44.45,11.49) v1(44.45,6.41) v1(44.99,60.13) v1(46.07,61.53) v1(46.99,54.67) v1(46.99,49.59) v1(46.99,44.51) v1(46.99,34.35) v1(46.99,24.19) v1(46.99,19.11) v1(46.99,14.03) v1(46.99,8.95) v1(47.09,61.53) v1(47.09,60.13) v1(48.1,61.53) v1(48.1,60.13) v1(48.93,58.46) v1(48.93,57.91) v1(48.93,57.37) v1(49.12,66.1) v1(49.12,65.21) v1(49.12,64.33) v1(49.12,62.67) v1(49.12,60.13) v1(49.53,52.13) v1(49.53,26.73) v1(49.53,21.65) v1(49.53,16.57) v1(49.53,11.49) v1(49.53,6.41) v1(50.13,66.1) v1(50.13,65.21) v1(50.13,64.33) v1(50.13,62.67) v1(50.13,60.13) v1(52.07,34.35) v1(52.07,24.19) v1(52.07,19.11) v1(52.07,14.03) v1(52.07,8.95) v1(54.61,47.05) v1(54.61,26.73) v1(54.61,21.65) v1(54.61,16.57) v1(54.61,11.49) v1(54.61,6.41) v1(55.28,65.6) v1(56.07,3.16) v1(56.07,2.4) v1(56.07,1.64) v1(57.15,54.67) v1(57.15,49.59) v1(57.15,39.43) v1(57.15,29.27) v1(57.15,24.19) v1(57.15,19.11) v1(57.15,14.03) v1(57.15,8.95) v1(58.78,59.27) v1(59.69,61.79) v1(59.69,36.89) v1(59.69,31.81) v1(59.69,26.73) v1(59.69,21.65) v1(59.69,16.57) v1(59.69,11.49) v1(62.23,34.35) v1(62.23,29.27) v1(62.23,24.19) v1(62.23,19.11) v1(62.23,14.03) v1(62.23,8.95) v1(64.77,52.13) v1(64.77,6.41) v1(64.77,1.33) v1(65.6,53.34) v1(65.6,48.26) v1(65.6,38.1) v1(65.6,33.02) v1(65.6,12.7) v1(65.91,40.58) v1(65.91,16.95) v1(66.04,43.75) v1(66.04,36.13) v1(66.04,29.78) v1(66.04,22.16) v1(66.04,10.73) v1(66.04,6.92) v1(67.31,64.83) v1(67.31,52.64) v1(67.31,51.37) v1(67.31,46.29) v1(67.31,34.86) v1(67.31,25.97) v1(67.31,23.43) v1(67.31,19.62) v1(67.31,14.54) v1(67.31,10.73) v1(67.31,8.19) v1(67.31,5.65) v1(68.14,55.88) v1(68.58,48.83) v1(68.58,42.48) v1(68.58,37.4) v1(68.58,31.05) v1(68.58,27.24) v1(68.58,15.81) v1(68.83,19.62) v1(69.85,1.33) v1(70.1,10.73) v1(70.68,53.34) v1(70.68,48.26) v1(70.68,38.1) v1(70.68,27.94) v1(70.68,22.86) v1(70.74,12.64) v1(71.12,36.13) v1(71.12,32.32) v1(71.12,20.89) v1(71.12,6.92) v1(72.39,59.75) v1(72.39,52.64) v1(72.39,50.1) v1(72.39,47.56) v1(72.39,42.48) v1(72.39,39.94) v1(72.39,33.59) v1(72.39,29.78) v1(72.39,23.43) v1(72.39,18.35) v1(72.39,13.27) v1(72.39,8.19) v1(73.22,55.88) v1(73.66,51.37) v1(73.66,45.02) v1(73.66,43.75) v1(73.66,38.67) v1(73.66,34.86) v1(73.66,31.05) v1(73.66,25.97) v1(73.66,20.89) v1(73.66,10.73) v1(73.66,8.19) v1(73.66,5.65) v1(73.72,15.88) v1(74.93,67.37) v1(74.93,57.21) v1(74.93,52.13) v1(74.93,47.05) v1(74.93,41.97) v1(74.93,36.89) v1(74.93,31.81) v1(74.93,26.73) v1(74.93,21.65) v1(74.93,16.57) v1(74.93,11.49) v1(74.93,6.41) v1(74.93,1.33) v2(34.46,41.74) v2(34.46,40.94) v2(34.46,38.54) v2(34.46,36.14) v2(34.46,35.34) v2(36.86,38.54) v2(37.66,38.54) v2(37.66,36.94) v2(39.26,40.14) v2(40.06,41.74) v2(40.06,40.94) v2(40.06,39.34) v2(40.06,38.54) v2(40.06,37.74) v2(40.06,36.94) v2(40.06,36.14) v2(40.06,35.34) v2(40.86,41.74) v2(40.86,35.34)
